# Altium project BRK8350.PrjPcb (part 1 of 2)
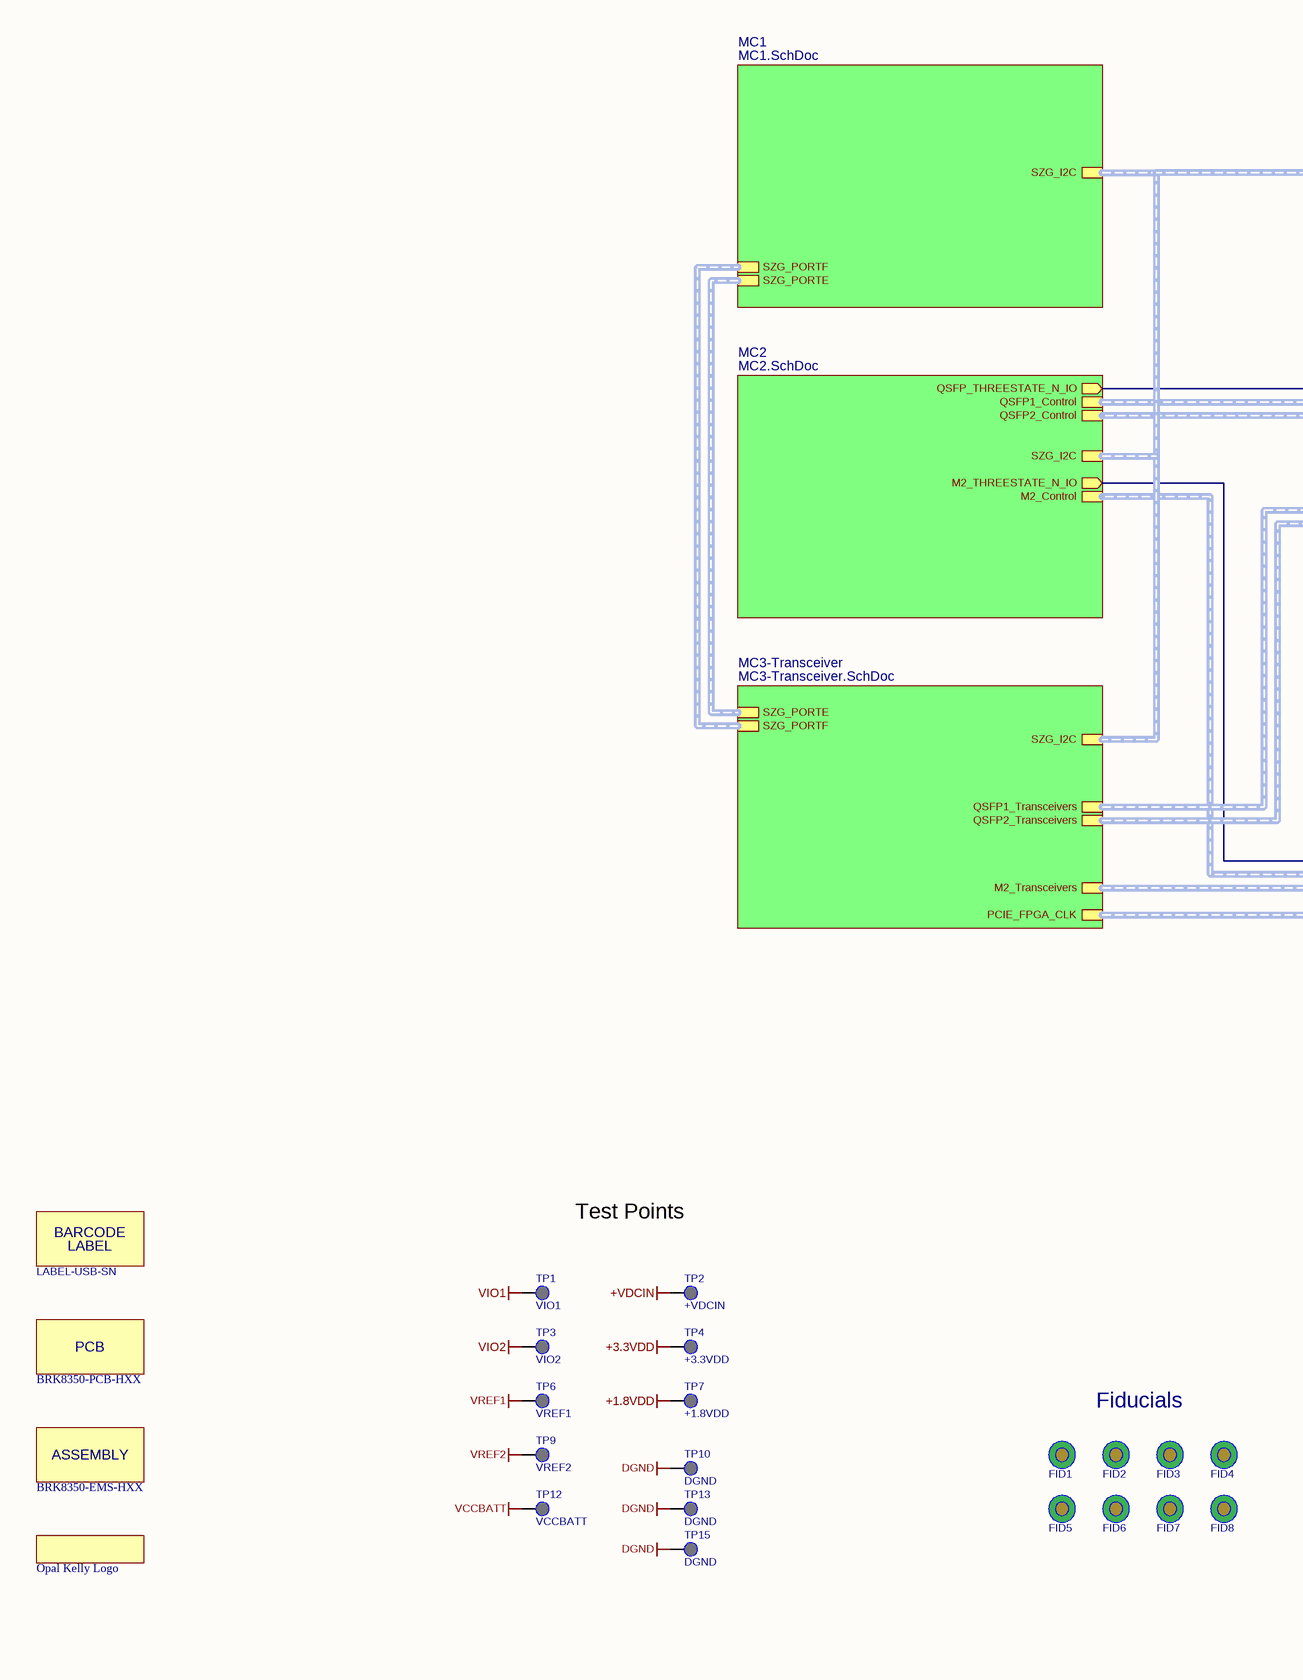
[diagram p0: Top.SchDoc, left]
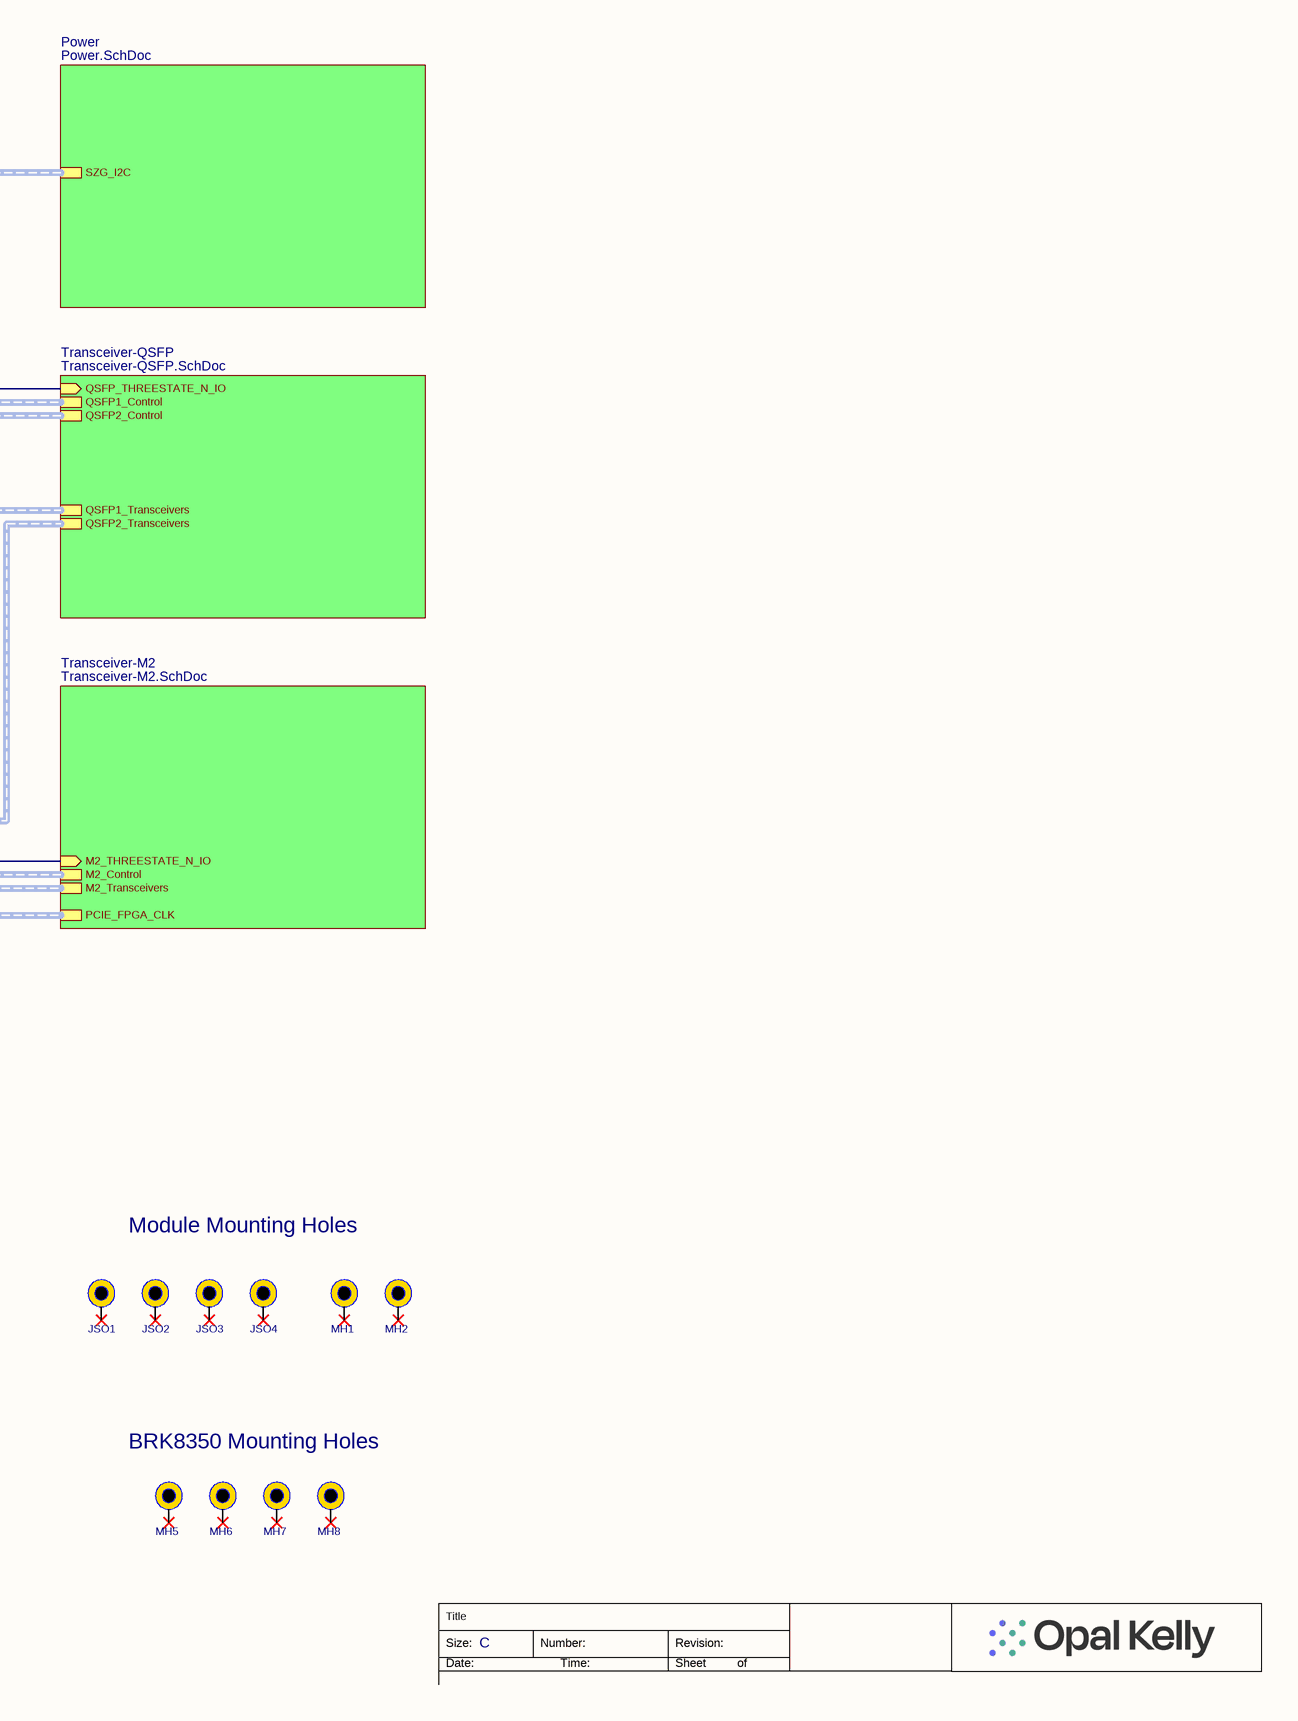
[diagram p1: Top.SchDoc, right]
VariantBoms: Default=001770; PCB_Revision: H; Part_Number: BRK8350; BOM_Revision: 02
7 sheets, 293 parts. Net scope: hierarchical (ports join the sheet entries above them; power ports are global).
Board file: BRK8350.PcbDoc
Sheets:
  Top.SchDoc
    Transceiver-QSFP = Transceiver-QSFP.SchDoc
    MC2 = MC2.SchDoc
    MC1 = MC1.SchDoc
    Power = Power.SchDoc
    Transceiver-M2 = Transceiver-M2.SchDoc
    MC3-Transceiver = MC3-Transceiver.SchDoc

## Sheet Top.SchDoc: BRK8350 - Top Level
size C; Organization: Opal Kelly; Address1: 13500 SW 72nd Ave STE 100; Address3: Portland, OR  97223; Address4: http://www.opalkelly.com; DocumentNumber: 1; Revision: 1; SheetNumber: 1; SheetTotal: 7; PageSetup: Record=PageOptions¦CenterHorizontal=True¦CenterVertical=True¦PrintScale=0.52¦XCorrection=1.00¦YCorrection=1.00¦PrintKind=0¦BorderSize=5000000¦LeftOffset=0¦BottomOffset=0¦Orientation=2¦PaperLength=1000¦PaperWidth=1000¦Scale=100¦PaperSource=15¦PrintQuality=600¦MediaType=1¦DitherType=10¦PaperKind=Letter¦PrintScaleMode=1

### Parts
*1  Opal Kelly Logo  [okLogo-23x5-2021]
ASSY1  BRK8350-EMS-HXX  (mechanical)
FID1  FIDUCIAL  [FID1MM/2MM-SS]  (value not drawn)
FID2  FIDUCIAL  [FID1MM/2MM-SS]  (value not drawn)
FID3  FIDUCIAL  [FID1MM/2MM-SS]  (value not drawn)
FID4  FIDUCIAL  [FID1MM/2MM-SS]  (value not drawn)
FID5  FIDUCIAL  [FID1MM/2MM-SS]  (value not drawn)
FID6  FIDUCIAL  [FID1MM/2MM-SS]  (value not drawn)
FID7  FIDUCIAL  [FID1MM/2MM-SS]  (value not drawn)
FID8  FIDUCIAL  [FID1MM/2MM-SS]  (value not drawn)
JSO1  Jack Screw Standoff  [JSO-0515-01]  (value not drawn)
JSO2  Jack Screw Standoff  [JSO-0515-01]  (value not drawn)
JSO3  Jack Screw Standoff  [JSO-0515-01]  (value not drawn)
JSO4  Jack Screw Standoff  [JSO-0515-01]  (value not drawn)
LABEL1  LABEL-USB-SN  (mechanical)
MH1  MTG  [MTG-3.2/6.5-PTH]  (value not drawn)
MH2  MTG  [MTG-3.2/6.5-PTH]  (value not drawn)
MH5  MTG  [MTG-3.2/6.5-PTH]  (value not drawn)
MH6  MTG  [MTG-3.2/6.5-PTH]  (value not drawn)
MH7  MTG  [MTG-3.2/6.5-PTH]  (value not drawn)
MH8  MTG  [MTG-3.2/6.5-PTH]  (value not drawn)
PCB1  BRK8350-PCB-HXX  (mechanical)
TP1  VIO1  [TP-PTH-65/100]
TP2  +VDCIN  [TP-PTH-65/100]
TP3  VIO2  [TP-PTH-65/100]
TP4  +3.3VDD  [TP-PTH-65/100]
TP6  VREF1  [TP-PTH-65/100]
TP7  +1.8VDD  [TP-PTH-65/100]
TP9  VREF2  [TP-PTH-65/100]
TP10  DGND  [TP-PTH-65/100]
TP12  VCCBATT  [TP-PTH-65/100]
TP13  DGND  [TP-PTH-65/100]
TP15  DGND  [TP-PTH-65/100]

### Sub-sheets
MC1 = MC1.SchDoc: SZG_I2C (harness I2C), SZG_PORTF (harness SYZYGY_TXR4), SZG_PORTE (harness SYZYGY_TXR4)
MC2 = MC2.SchDoc: QSFP1_Control (harness QSFP_Control), M2_Control (harness M2_Control), QSFP2_Control (harness QSFP_Control), SZG_I2C (harness I2C), QSFP_THREESTATE_N_IO (out), M2_THREESTATE_N_IO (out)
MC3-Transceiver = MC3-Transceiver.SchDoc: SZG_PORTF (harness SYZYGY_TXR4), SZG_PORTE (harness SYZYGY_TXR4), SZG_I2C (harness I2C), M2_Transceivers (harness M2_Transceivers), QSFP1_Transceivers (harness QSFP_Transceivers), QSFP2_Transceivers (harness QSFP_Transceivers), PCIE_FPGA_CLK (harness CLK)
Power = Power.SchDoc: SZG_I2C (harness I2C)
Transceiver-M2 = Transceiver-M2.SchDoc: M2_Transceivers (harness M2_Transceivers), M2_Control (harness M2_Control), PCIE_FPGA_CLK (harness CLK), M2_THREESTATE_N_IO (in)
Transceiver-QSFP = Transceiver-QSFP.SchDoc: QSFP1_Control (harness QSFP_Control), QSFP2_Control (harness QSFP_Control), QSFP1_Transceivers (harness QSFP_Transceivers), QSFP2_Transceivers (harness QSFP_Transceivers), QSFP_THREESTATE_N_IO (in)

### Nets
+1.8VDD: TP7.1(PIN)
+3.3VDD: TP4.1(PIN)
+VDCIN: TP2.1(PIN)
DGND: TP10.1(PIN) TP13.1(PIN) TP15.1(PIN)
VCCBATT: TP12.1(PIN)
VIO1: TP1.1(PIN)
VIO2: TP3.1(PIN)
VREF1: TP6.1(PIN)
VREF2: TP9.1(PIN)
M2_THREESTATE_N_IO: sheet MC2/M2_THREESTATE_N_IO, sheet Transceiver-M2/M2_THREESTATE_N_IO
QSFP_THREESTATE_N_IO: sheet Transceiver-QSFP/QSFP_THREESTATE_N_IO, sheet MC2/QSFP_THREESTATE_N_IO

Not connected (* = marked no-connect by the designer): JSO1 1*; JSO2 1*; JSO3 1*; JSO4 1*; MH1 1*; MH2 1*; MH5 1*; MH6 1*; MH7 1*; MH8 1*

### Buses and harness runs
harness sheet MC1/SZG_I2C = sheet MC2/SZG_I2C = sheet MC3-Transceiver/SZG_I2C = sheet Power/SZG_I2C
harness sheet MC1/SZG_PORTE = sheet MC3-Transceiver/SZG_PORTE
harness sheet MC1/SZG_PORTF = sheet MC3-Transceiver/SZG_PORTF
harness sheet MC2/M2_Control = sheet Transceiver-M2/M2_Control
harness sheet MC2/QSFP1_Control = sheet Transceiver-QSFP/QSFP1_Control
harness sheet MC2/QSFP2_Control = sheet Transceiver-QSFP/QSFP2_Control
harness sheet MC3-Transceiver/M2_Transceivers = sheet Transceiver-M2/M2_Transceivers
harness sheet MC3-Transceiver/PCIE_FPGA_CLK = sheet Transceiver-M2/PCIE_FPGA_CLK
harness sheet MC3-Transceiver/QSFP1_Transceivers = sheet Transceiver-QSFP/QSFP1_Transceivers
harness sheet MC3-Transceiver/QSFP2_Transceivers = sheet Transceiver-QSFP/QSFP2_Transceivers

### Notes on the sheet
- Test Points
- Module Mounting Holes
- Fiducials
- BRK8350 Mounting Holes
- Title
- Size:
- Date:
- C
- Number:
- Time:
- Revision:
- Sheet
- of

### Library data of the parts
*1 = OKLOGO: partnumber: ALIGNI_IGNORE
ASSY1 = 002490: BRK8350 PCB assembly; Partnumber: 002490; Manufacturer: PCB Assembly Cost
FID1-FID8 = FIDUCIAL: PCB fiducial; partnumber: ALIGNI_IGNORE
JSO1-JSO4 = 001879: Mounting hole; Partnumber: 001879; manufacturer: Samtec
LABEL1 = 000605: Barcode label; Partnumber: 000605; manufacturer: Generic Printer
MH1 MH2 MH5-MH8 = MTG: Mounting hole; partnumber: ALIGNI_IGNORE
PCB1 = 002491: PCB for BRK8350; Partnumber: 002491; Manufacturer: Generic PCB Manufacturer
TP1-TP4 TP6 TP7 TP9 TP10 TP12 TP13 TP15 = TP-PTH-65/100: Test point, plated through-hole, 65/100mil; partnumber: ALIGNI_IGNORE

## Sheet Transceiver-QSFP.SchDoc: BRK8350 - QSFP
size C; Author: Casey Smith; Organization: Opal Kelly; Address1: 13500 SW 72nd Ave STE 100; Address2: Portland, OR 97223; Address3: 217.391.3724; Address4: http://www.opalkelly.com; DocumentNumber: 5; Revision: 1; SheetNumber: 5; SheetTotal: 7
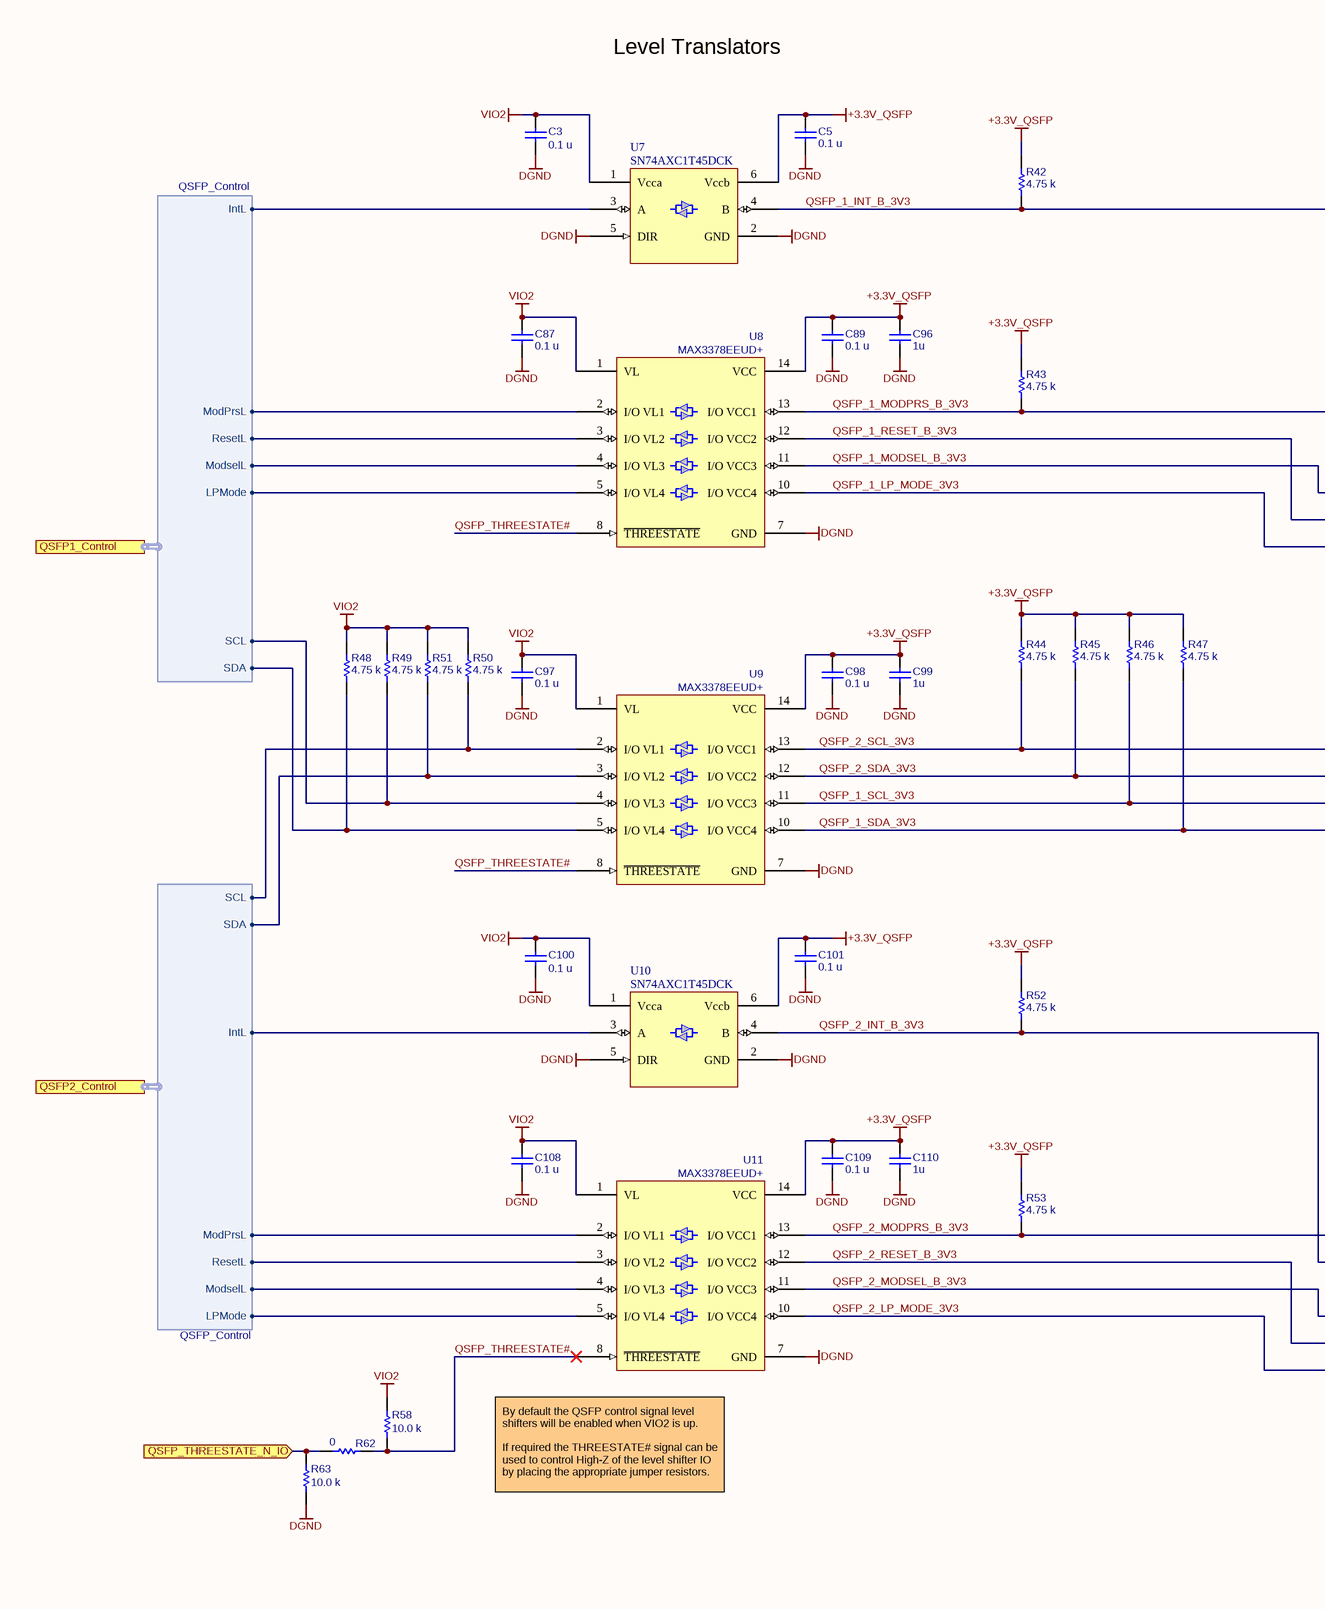
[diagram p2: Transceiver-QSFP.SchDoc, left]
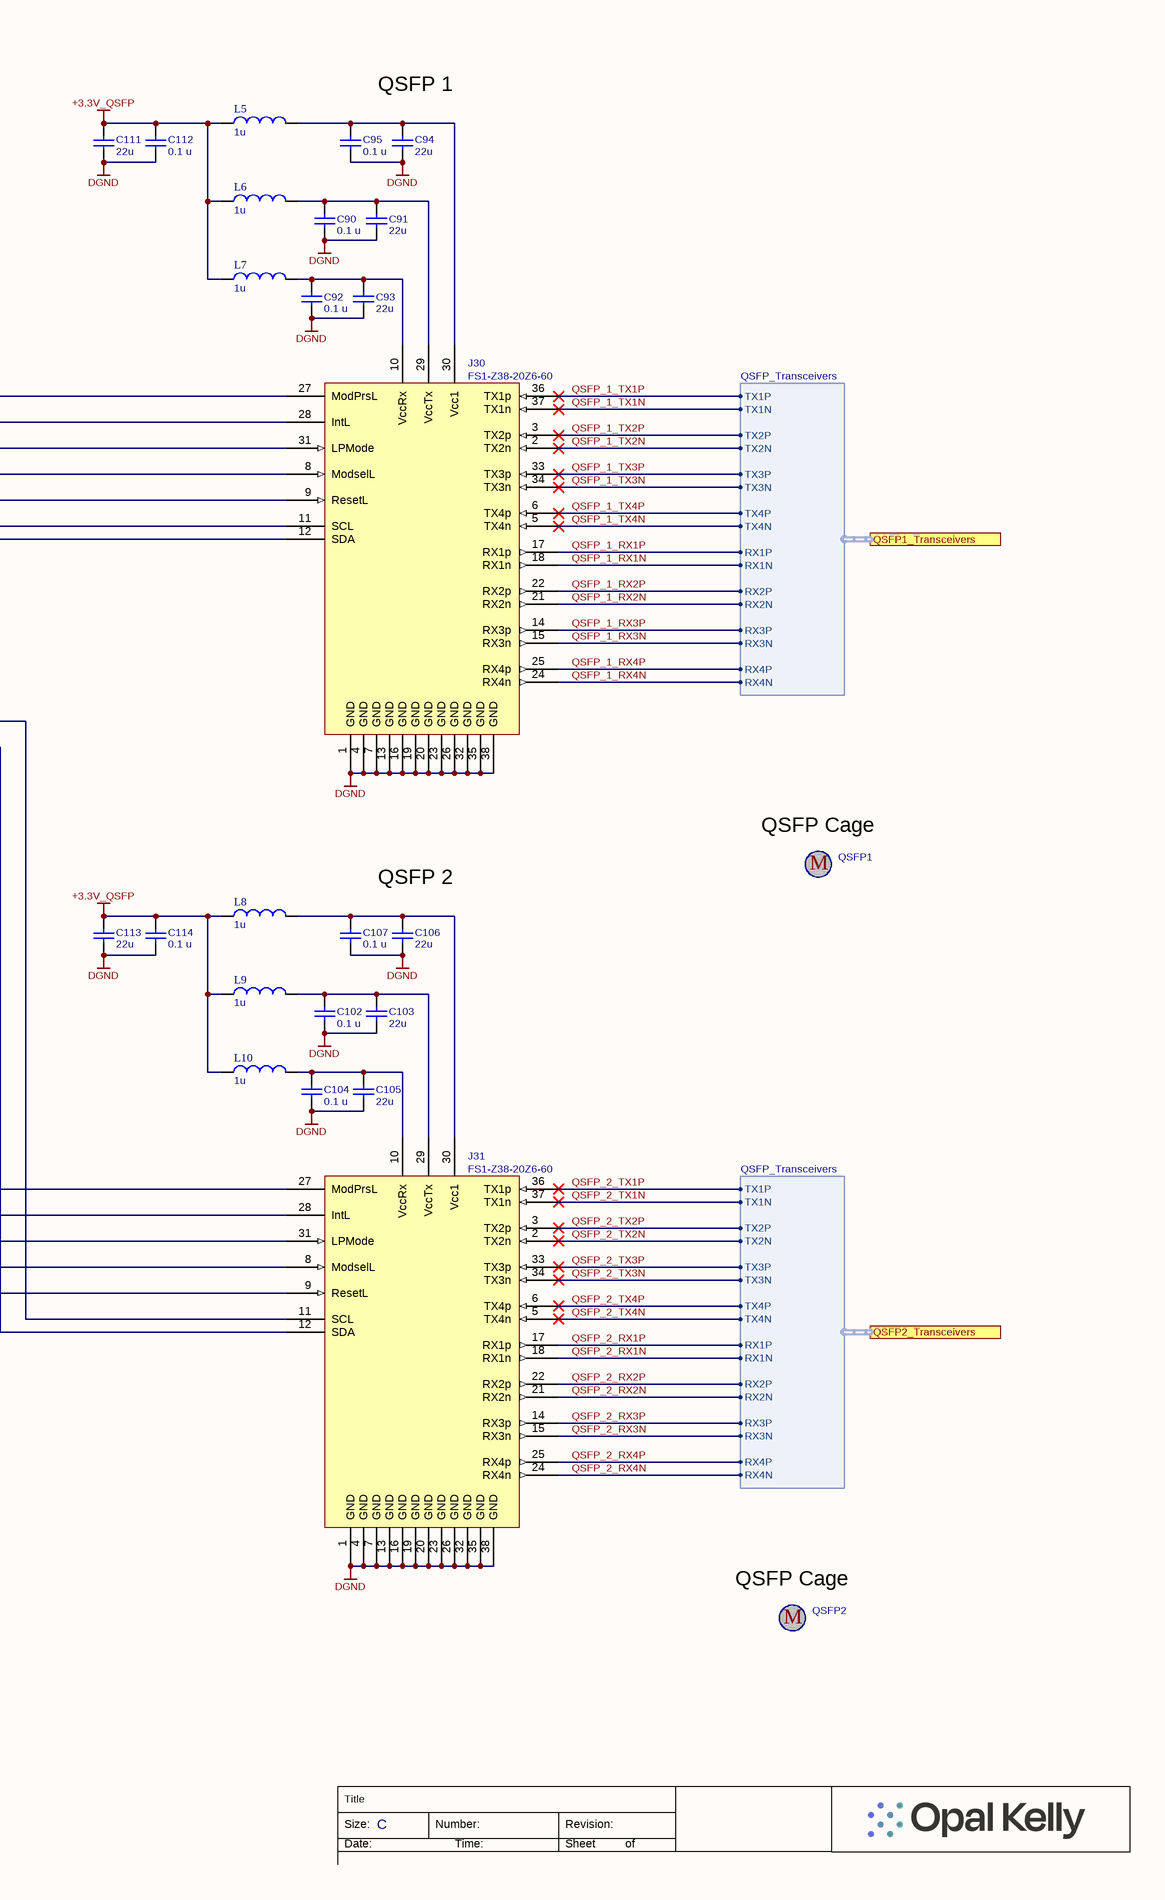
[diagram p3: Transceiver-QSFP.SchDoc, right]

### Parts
C3  value 0.1 u  [CAPC1005X06A]  (hidden comment: C0402C104K8PACTU)
C5  value 0.1 u  [CAPC1005X06A]  (hidden comment: C0402C104K8PACTU)
C87  value 0.1 u  [CAPC1005X06A]  (hidden comment: C0402C104K8PACTU)
C89  value 0.1 u  [CAPC1005X06A]  (hidden comment: C0402C104K8PACTU)
C90  value 0.1 u  [CAPC1005X06A]  (hidden comment: SM-0402, 10%, 10v)
C91  value 22u  [CAPC3216N]  (hidden comment: SM-1206, 10%, 10v, X7R)
C92  value 0.1 u  [CAPC1005X06A]  (hidden comment: SM-0402, 10%, 10v)
C93  value 22u  [CAPC3216N]  (hidden comment: SM-1206, 10%, 10v, X7R)
C94  value 22u  [CAPC3216N]  (hidden comment: SM-1206, 10%, 10v, X7R)
C95  value 0.1 u  [CAPC1005X06A]  (hidden comment: SM-0402, 10%, 10v)
C96  value 1u  [CAPC1005X06A]  (hidden comment: LMK105BJ105KV-F)
C97  value 0.1 u  [CAPC1005X06A]  (hidden comment: C0402C104K8PACTU)
C98  value 0.1 u  [CAPC1005X06A]  (hidden comment: C0402C104K8PACTU)
C99  value 1u  [CAPC1005X06A]  (hidden comment: LMK105BJ105KV-F)
C100  value 0.1 u  [CAPC1005X06A]  (hidden comment: C0402C104K8PACTU)
C101  value 0.1 u  [CAPC1005X06A]  (hidden comment: C0402C104K8PACTU)
C102  value 0.1 u  [CAPC1005X06A]  (hidden comment: SM-0402, 10%, 10v)
C103  value 22u  [CAPC3216N]  (hidden comment: SM-1206, 10%, 10v, X7R)
C104  value 0.1 u  [CAPC1005X06A]  (hidden comment: SM-0402, 10%, 10v)
C105  value 22u  [CAPC3216N]  (hidden comment: SM-1206, 10%, 10v, X7R)
C106  value 22u  [CAPC3216N]  (hidden comment: SM-1206, 10%, 10v, X7R)
C107  value 0.1 u  [CAPC1005X06A]  (hidden comment: SM-0402, 10%, 10v)
C108  value 0.1 u  [CAPC1005X06A]  (hidden comment: C0402C104K8PACTU)
C109  value 0.1 u  [CAPC1005X06A]  (hidden comment: C0402C104K8PACTU)
C110  value 1u  [CAPC1005X06A]  (hidden comment: LMK105BJ105KV-F)
C111  value 22u  [CAPC3216N]  (hidden comment: SM-1206, 10%, 10v, X7R)
C112  value 0.1 u  [CAPC1005X06A]  (hidden comment: SM-0402, 10%, 10v)
C113  value 22u  [CAPC3216N]  (hidden comment: SM-1206, 10%, 10v, X7R)
C114  value 0.1 u  [CAPC1005X06A]  (hidden comment: SM-0402, 10%, 10v)
J30  FS1-Z38-20Z6-60  [QSFP28_RECEPTACLE_SFF-8679]
J31  FS1-Z38-20Z6-60  [QSFP28_RECEPTACLE_SFF-8679]
L5  value 1u  [CIGT252010]  (hidden comment: CIGT252010LM1R0MNE)
L6  value 1u  [CIGT252010]  (hidden comment: CIGT252010LM1R0MNE)
L7  value 1u  [CIGT252010]  (hidden comment: CIGT252010LM1R0MNE)
L8  value 1u  [CIGT252010]  (hidden comment: CIGT252010LM1R0MNE)
L9  value 1u  [CIGT252010]  (hidden comment: CIGT252010LM1R0MNE)
L10  value 1u  [CIGT252010]  (hidden comment: CIGT252010LM1R0MNE)
QSFP1  Pressfit  [QSFP28_SINGLE_CAGE]  (value not drawn)
QSFP2  Pressfit  [QSFP28_SINGLE_CAGE]  (value not drawn)
R42  value 4.75 k  [RESC1005X06A]  (hidden comment: CRCW04024K75FKED)
R43  value 4.75 k  [RESC1005X06A]  (hidden comment: CRCW04024K75FKED)
R44  value 4.75 k  [RESC1005X06A]  (hidden comment: CRCW04024K75FKED)
R45  value 4.75 k  [RESC1005X06A]  (hidden comment: CRCW04024K75FKED)
R46  value 4.75 k  [RESC1005X06A]  (hidden comment: CRCW04024K75FKED)
R47  value 4.75 k  [RESC1005X06A]  (hidden comment: CRCW04024K75FKED)
R48  value 4.75 k  [RESC1005X06A]  (hidden comment: CRCW04024K75FKED)
R49  value 4.75 k  [RESC1005X06A]  (hidden comment: CRCW04024K75FKED)
R50  value 4.75 k  [RESC1005X06A]  (hidden comment: CRCW04024K75FKED)
R51  value 4.75 k  [RESC1005X06A]  (hidden comment: CRCW04024K75FKED)
R52  value 4.75 k  [RESC1005X06A]  (hidden comment: CRCW04024K75FKED)
R53  value 4.75 k  [RESC1005X06A]  (hidden comment: CRCW04024K75FKED)
R58  value 10.0 k  [RESC1005X06A]  (hidden comment: CRCW040210K0FKED)
R62  value 0  [RESC1005X06A]  (hidden comment: SM-0402, 1%, 1/16W)
R63  value 10.0 k  [RESC1005X06A]  (hidden comment: CRCW040210K0FKED)
U7  SN74AXC1T45DCK  [DCK-R-PDSO-G6]
U8  MAX3378EEUD+  [MAX3378EEUD+]
U9  MAX3378EEUD+  [MAX3378EEUD+]
U10  SN74AXC1T45DCK  [DCK-R-PDSO-G6]
U11  MAX3378EEUD+  [MAX3378EEUD+]

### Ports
QSFP1_Control (harness QSFP_Control), QSFP1_Transceivers (harness QSFP_Transceivers), QSFP2_Control (harness QSFP_Control), QSFP2_Transceivers (harness QSFP_Transceivers), QSFP_THREESTATE_N_IO (in)

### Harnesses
QSFP_Transceivers: TX1P, TX1N, TX2P, TX2N, TX3P, TX3N, TX4P, TX4N, RX1P, RX1N, RX2P, RX2N, RX3P, RX3N, RX4P, RX4N
QSFP_Control: ModPrsL, IntL, LPMode, ModselL, ResetL, SCL, SDA

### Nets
+3.3V_QSFP: C5.2 C89.2 C96.2 C98.2 C99.2 C101.2 C109.2 C110.2 C111.2 C112.2 C113.2 C114.2 L5.1 L6.1 L7.1 L8.1 L9.1 L10.1 R42.2 R43.2 R44.2 R45.2 R46.2 R47.2 R52.2 R53.2 U7.6(Vccb) U8.14(VCC) U9.14(VCC) U10.6(Vccb) U11.14(VCC)
DGND: C3.1 C5.1 C87.1 C89.1 C90.1 C91.1 C92.1 C93.1 C94.1 C95.1 C96.1 C97.1 C98.1 C99.1 C100.1 C101.1 C102.1 C103.1 C104.1 C105.1 C106.1 C107.1 C108.1 C109.1 C110.1 C111.1 C112.1 C113.1 C114.1 J30.1(GND) J30.4(GND) J30.7(GND) J30.13(GND) J30.16(GND) J30.19(GND) J30.20(GND) J30.23(GND) J30.26(GND) J30.32(GND) J30.35(GND) J30.38(GND) J31.1(GND) J31.4(GND) J31.7(GND) J31.13(GND) J31.16(GND) J31.19(GND) J31.20(GND) J31.23(GND) J31.26(GND) J31.32(GND) J31.35(GND) J31.38(GND) R63.1 U7.2(GND) U7.5(DIR) U8.7(GND) U9.7(GND) U10.2(GND) U10.5(DIR) U11.7(GND)
VIO2: C3.2 C87.2 C97.2 C100.2 C108.2 R48.2 R49.2 R50.2 R51.2 R58.2 U7.1(Vcca) U8.1(VL) U9.1(VL) U10.1(Vcca) U11.1(VL)
QSFP_1_INT_B: U7.3(A) ; port QSFP1_Control.IntL
QSFP_1_INT_B_3V3: J30.28(IntL) R42.1 U7.4(B)
QSFP_1_LP_MODE: U8.5(I/O_VL4) ; port QSFP1_Control.LPMode
QSFP_1_LP_MODE_3V3: J30.31(LPMode) U8.10(I/O_VCC4)
QSFP_1_MODPRS_B: U8.2(I/O_VL1) ; port QSFP1_Control.ModPrsL
QSFP_1_MODPRS_B_3V3: J30.27(ModPrsL) R43.1 U8.13(I/O_VCC1)
QSFP_1_MODSEL_B: U8.4(I/O_VL3) ; port QSFP1_Control.ModselL
QSFP_1_MODSEL_B_3V3: J30.8(ModselL) U8.11(I/O_VCC3)
QSFP_1_RESET_B: U8.3(I/O_VL2) ; port QSFP1_Control.ResetL
QSFP_1_RESET_B_3V3: J30.9(ResetL) U8.12(I/O_VCC2)
QSFP_1_RX1N: J30.18(RX1n) ; port QSFP1_Transceivers.RX1N
QSFP_1_RX1P: J30.17(RX1p) ; port QSFP1_Transceivers.RX1P
QSFP_1_RX2N: J30.21(RX2n) ; port QSFP1_Transceivers.RX2N
QSFP_1_RX2P: J30.22(RX2p) ; port QSFP1_Transceivers.RX2P
QSFP_1_RX3N: J30.15(RX3n) ; port QSFP1_Transceivers.RX3N
QSFP_1_RX3P: J30.14(RX3p) ; port QSFP1_Transceivers.RX3P
QSFP_1_RX4N: J30.24(RX4n) ; port QSFP1_Transceivers.RX4N
QSFP_1_RX4P: J30.25(RX4p) ; port QSFP1_Transceivers.RX4P
QSFP_1_SCL: R49.1 U9.4(I/O_VL3) ; port QSFP1_Control.SCL
QSFP_1_SCL_3V3: J30.11(SCL) R46.1 U9.11(I/O_VCC3)
QSFP_1_SDA: R48.1 U9.5(I/O_VL4) ; port QSFP1_Control.SDA
QSFP_1_SDA_3V3: J30.12(SDA) R47.1 U9.10(I/O_VCC4)
QSFP_1_TX1N: J30.37(TX1n) ; port QSFP1_Transceivers.TX1N
QSFP_1_TX1P: J30.36(TX1p) ; port QSFP1_Transceivers.TX1P
QSFP_1_TX2N: J30.2(TX2n) ; port QSFP1_Transceivers.TX2N
QSFP_1_TX2P: J30.3(TX2p) ; port QSFP1_Transceivers.TX2P
QSFP_1_TX3N: J30.34(TX3n) ; port QSFP1_Transceivers.TX3N
QSFP_1_TX3P: J30.33(TX3p) ; port QSFP1_Transceivers.TX3P
QSFP_1_TX4N: J30.5(TX4n) ; port QSFP1_Transceivers.TX4N
QSFP_1_TX4P: J30.6(TX4p) ; port QSFP1_Transceivers.TX4P
QSFP_2_INT_B: U10.3(A) ; port QSFP2_Control.IntL
QSFP_2_INT_B_3V3: J31.28(IntL) R52.1 U10.4(B)
QSFP_2_LP_MODE: U11.5(I/O_VL4) ; port QSFP2_Control.LPMode
QSFP_2_LP_MODE_3V3: J31.31(LPMode) U11.10(I/O_VCC4)
QSFP_2_MODPRS_B: U11.2(I/O_VL1) ; port QSFP2_Control.ModPrsL
QSFP_2_MODPRS_B_3V3: J31.27(ModPrsL) R53.1 U11.13(I/O_VCC1)
QSFP_2_MODSEL_B: U11.4(I/O_VL3) ; port QSFP2_Control.ModselL
QSFP_2_MODSEL_B_3V3: J31.8(ModselL) U11.11(I/O_VCC3)
QSFP_2_RESET_B: U11.3(I/O_VL2) ; port QSFP2_Control.ResetL
QSFP_2_RESET_B_3V3: J31.9(ResetL) U11.12(I/O_VCC2)
QSFP_2_RX1N: J31.18(RX1n) ; port QSFP2_Transceivers.RX1N
QSFP_2_RX1P: J31.17(RX1p) ; port QSFP2_Transceivers.RX1P
QSFP_2_RX2N: J31.21(RX2n) ; port QSFP2_Transceivers.RX2N
QSFP_2_RX2P: J31.22(RX2p) ; port QSFP2_Transceivers.RX2P
QSFP_2_RX3N: J31.15(RX3n) ; port QSFP2_Transceivers.RX3N
QSFP_2_RX3P: J31.14(RX3p) ; port QSFP2_Transceivers.RX3P
QSFP_2_RX4N: J31.24(RX4n) ; port QSFP2_Transceivers.RX4N
QSFP_2_RX4P: J31.25(RX4p) ; port QSFP2_Transceivers.RX4P
QSFP_2_SCL: R50.1 U9.2(I/O_VL1) ; port QSFP2_Control.SCL
QSFP_2_SCL_3V3: J31.11(SCL) R44.1 U9.13(I/O_VCC1)
QSFP_2_SDA: R51.1 U9.3(I/O_VL2) ; port QSFP2_Control.SDA
QSFP_2_SDA_3V3: J31.12(SDA) R45.1 U9.12(I/O_VCC2)
QSFP_2_TX1N: J31.37(TX1n) ; port QSFP2_Transceivers.TX1N
QSFP_2_TX1P: J31.36(TX1p) ; port QSFP2_Transceivers.TX1P
QSFP_2_TX2N: J31.2(TX2n) ; port QSFP2_Transceivers.TX2N
QSFP_2_TX2P: J31.3(TX2p) ; port QSFP2_Transceivers.TX2P
QSFP_2_TX3N: J31.34(TX3n) ; port QSFP2_Transceivers.TX3N
QSFP_2_TX3P: J31.33(TX3p) ; port QSFP2_Transceivers.TX3P
QSFP_2_TX4N: J31.5(TX4n) ; port QSFP2_Transceivers.TX4N
QSFP_2_TX4P: J31.6(TX4p) ; port QSFP2_Transceivers.TX4P
QSFP_THREESTATE#: R58.1 R62.2 U8.8(~{THREESTATE}) U9.8(~{THREESTATE}) U11.8(~{THREESTATE})
QSFP_THREESTATE_N_IO: R62.1 R63.2 ; port QSFP_THREESTATE_N_IO
NetC90_2: C90.2 C91.2 J30.29(VccTx) L6.2
NetC92_2: C92.2 C93.2 J30.10(VccRx) L7.2
NetC94_2: C94.2 C95.2 J30.30(Vcc1) L5.2
NetC102_2: C102.2 C103.2 J31.29(VccTx) L9.2
NetC104_2: C104.2 C105.2 J31.10(VccRx) L10.2
NetC106_2: C106.2 C107.2 J31.30(Vcc1) L8.2

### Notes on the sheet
- Level Translators
- QSFP 1
- QSFP 2
- (near QSFP1) QSFP Cage
- (near U11) By default the QSFP control signal level shifters will be enabled when VIO2 is up.
  If required the THREESTATE# signal can be used to control High-Z of the level shifter IO by placing the appropriate jumper resistors.
- (near QSFP2) QSFP Cage
- Title
- Size:
- Date:
- C
- Number:
- Time:
- Revision:
- Sheet
- of

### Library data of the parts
C3 C5 C100 C101 = 001073: Partnumber: 000070; manufacturer: Kemet; ValueFloat: 1E-7; x_tolerance: 10
C87 C89 C97 C98 C108 C109 = 000070: Partnumber: 000070; manufacturer: Kemet; ValueFloat: 1E-7; x_tolerance: 10
C90 C92 C95 C102 C104 C107 C112 C114 = 000070: Partnumber: 000070; manufacturer: Kemet; manufacturer_pn: C0402C104K8PACTU; ValueFloat: 1E-7; id: 750; inventory_price: 0.0023; reorder_quantity: 70000; x_tolerance: 10
C91 C93 C94 C103 C105 C106 C111 C113 = 001284: Partnumber: 001284; manufacturer: Taiyo Yuden; manufacturer_pn: LMK316AB7226KL-TR; ValueFloat: 2.2E-5; id: 60625; inventory_price: 0.14; reorder_quantity: 4000; x_tolerance: 10
C96 C99 C110 = 000480: Partnumber: 000480; manufacturer: Taiyo Yuden; ValueFloat: 1E-6; x_tolerance: 10
J30 J31 = 001782: Partnumber: 001782; manufacturer: Amphenol; id: 254667; inventory_price: 4
L5-L10 = 002331: Thin Film, 1uH, 3.1A, 50mOhm, Unshielded; Partnumber: 002331; Manufacturer: Samsung Electro-Mechanics; ValueFloat: 1E-6; Tolerance (%): 20; Description 2: 1008 (2520 Metric)
QSFP1 QSFP2 = 001781: Partnumber: 001781; manufacturer: Amphenol; manufacturer_pn: U95-T111-1001; id: 254666; inventory_price: 3.5
R42-R53 = 001008: Partnumber: 001008; manufacturer: Vishay; ValueFloat: 4750; x_tolerance: 1
R58 R63 = 001521: Thick-film resistor; Manufacturer: Vishay; partnumber: 001521; Description 2: SM-0402, 1%, 1/16W; ValueFloat: 10000; Tolerance (%): 1; x_lifecycle_status: Production
R62 = 001713: Partnumber: 001713; manufacturer: Vishay; manufacturer_pn: CRCW04020000Z0EDC; id: 219362; inventory_price: 0.004; reorder_quantity: 20000; x_tolerance: 1
U7 U10 = 002140: Level Translator, 0.65V - 3.6V, Direction Control; Partnumber: 002140; Manufacturer: Texas Instruments; Description 2: Single Bit, Dual Supplies
U8 U9 U11 = 000178: Partnumber: 000178; manufacturer: Maxim

## Sheet MC2.SchDoc: BRK8350 - Mezzanine Connector MC2
size C; Author: Casey Smith; Organization: Opal Kelly; Address1: 13500 SW 72nd Ave STE 100; Address2: Portland, OR 97223; Address3: 217.391.3724; Address4: http://www.opalkelly.com; DocumentNumber: 3; Revision: 1; SheetNumber: 3; SheetTotal: 7
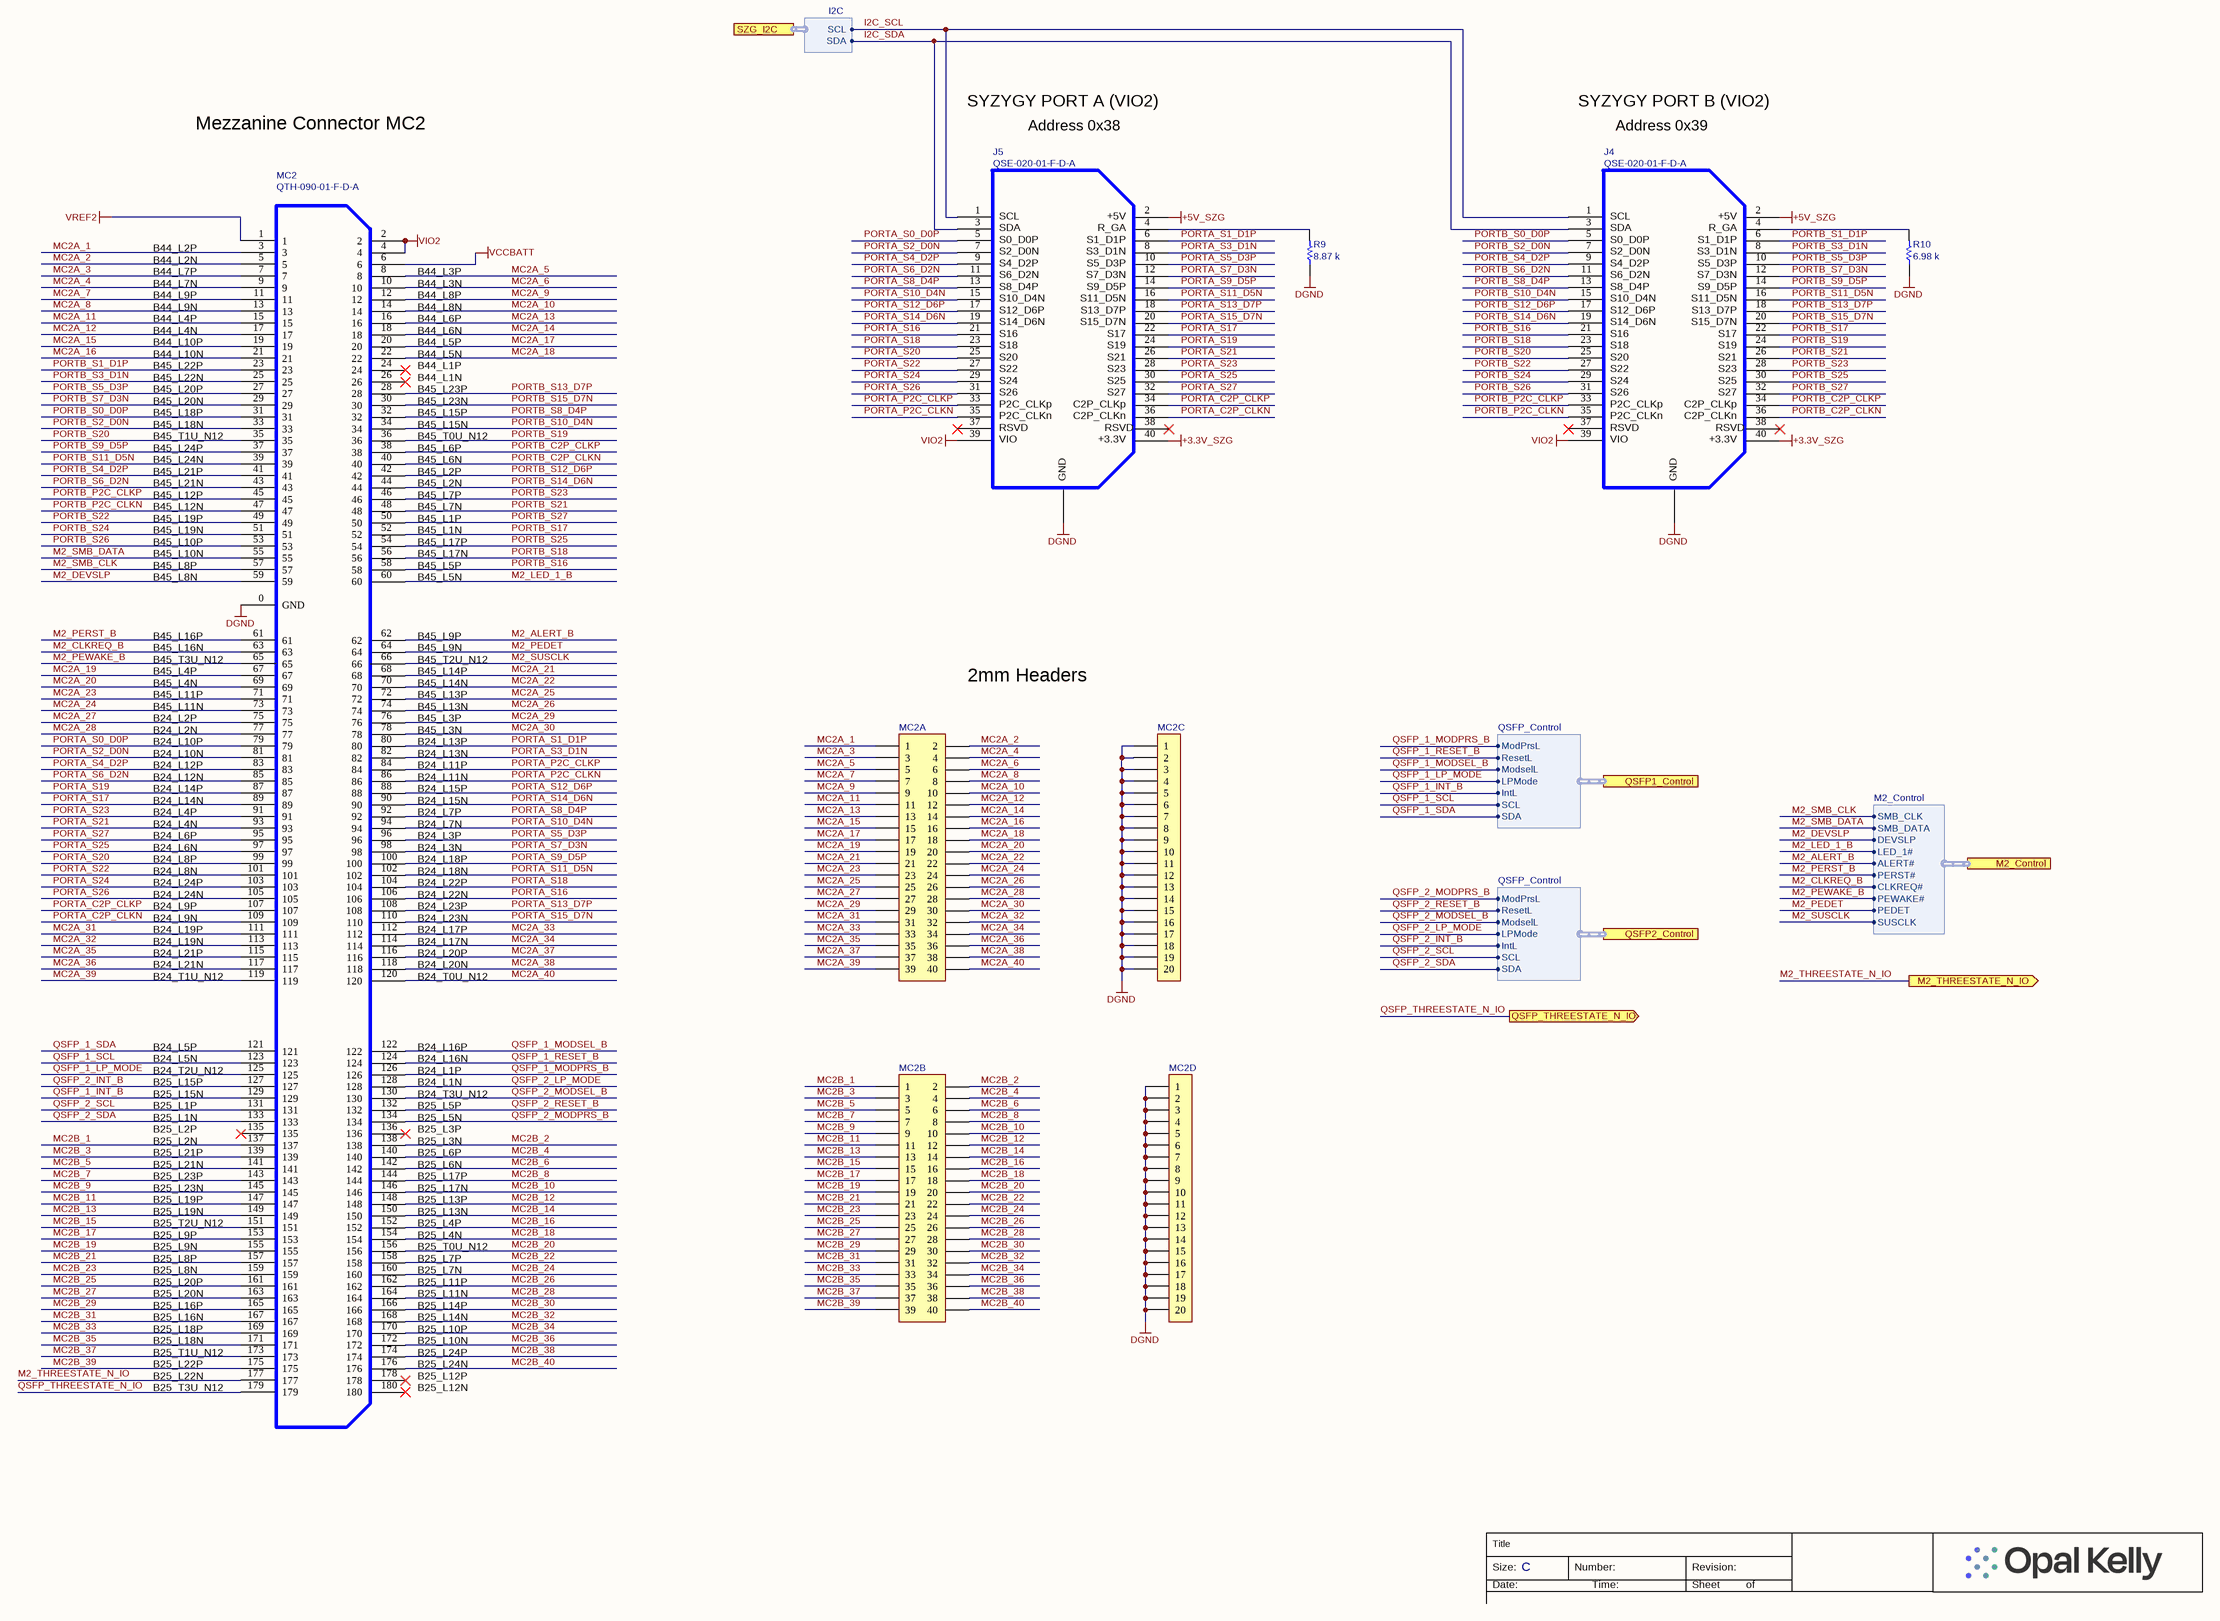
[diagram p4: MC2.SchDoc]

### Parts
J4  QSE-020-01-F-D-A  [QSE-020-01-X-D-A-L-SYZYGY]
J5  QSE-020-01-F-D-A  [QSE-020-01-X-D-A-L-SYZYGY]
MC2  QTH-090-01-F-D-A  [QTH-090-01-X-D]
MC2A  0877584016  [HDR2X20-2MM]  (value not drawn)
MC2B  0877584016  [HDR2X20-2MM]  (value not drawn)
MC2C  Header, 20-Pin, Single Row  [HDR1X20-2MM]  (value not drawn)
MC2D  Header, 20-Pin, Single Row  [HDR1X20-2MM]  (value not drawn)
R9  value 8.87 k  [RESC1005X06A]  (hidden comment: RC0402FR-078K87L)
R10  value 6.98 k  [RESC1005X06A]  (hidden comment: RC0402FR-076K98L)

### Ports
M2_Control (harness M2_Control), M2_THREESTATE_N_IO (out), QSFP1_Control (harness QSFP_Control), QSFP2_Control (harness QSFP_Control), QSFP_THREESTATE_N_IO (out), SZG_I2C (harness I2C)

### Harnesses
I2C: SCL, SDA
M2_Control: DEVSLP, SMB_CLK, SMB_DATA, ALERT#, PERST#, CLKREQ#, PEWAKE#, LED_1#, SUSCLK, PEDET
QSFP_Control: ModPrsL, IntL, LPMode, ModselL, ResetL, SCL, SDA

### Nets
+3.3V_SZG: J4.40 J5.40
+5V_SZG: J4.2 J5.2
DGND: J4.0 J5.0 MC2.0(GND) MC2C.1 MC2C.2 MC2C.3 MC2C.4 MC2C.5 MC2C.6 MC2C.7 MC2C.8 MC2C.9 MC2C.10 MC2C.11 MC2C.12 MC2C.13 MC2C.14 MC2C.15 MC2C.16 MC2C.17 MC2C.18 MC2C.19 MC2C.20 MC2D.1 MC2D.2 MC2D.3 MC2D.4 MC2D.5 MC2D.6 MC2D.7 MC2D.8 MC2D.9 MC2D.10 MC2D.11 MC2D.12 MC2D.13 MC2D.14 MC2D.15 MC2D.16 MC2D.17 MC2D.18 MC2D.19 MC2D.20 R9.1 R10.1
VCCBATT: MC2.6
VIO2: J4.39 J5.39 MC2.2 MC2.4
VREF2: MC2.1
I2C_SCL: J4.1 J5.1 ; port SZG_I2C.SCL
I2C_SDA: J4.3 J5.3 ; port SZG_I2C.SDA
M2_ALERT_B: MC2.62 ; port M2_Control.ALERT#
M2_CLKREQ_B: MC2.63 ; port M2_Control.CLKREQ#
M2_DEVSLP: MC2.59 ; port M2_Control.DEVSLP
M2_LED_1_B: MC2.60 ; port M2_Control.LED_1#
M2_PEDET: MC2.64 ; port M2_Control.PEDET
M2_PERST_B: MC2.61 ; port M2_Control.PERST#
M2_PEWAKE_B: MC2.65 ; port M2_Control.PEWAKE#
M2_SMB_CLK: MC2.57 ; port M2_Control.SMB_CLK
M2_SMB_DATA: MC2.55 ; port M2_Control.SMB_DATA
M2_SUSCLK: MC2.66 ; port M2_Control.SUSCLK
M2_THREESTATE_N_IO: MC2.177 ; port M2_THREESTATE_N_IO
MC2A_1: MC2.3 MC2A.1
MC2A_2: MC2.5 MC2A.2
MC2A_3: MC2.7 MC2A.3
MC2A_4: MC2.9 MC2A.4
MC2A_5: MC2.8 MC2A.5
MC2A_6: MC2.10 MC2A.6
MC2A_7: MC2.11 MC2A.7
MC2A_8: MC2.13 MC2A.8
MC2A_9: MC2.12 MC2A.9
MC2A_10: MC2.14 MC2A.10
MC2A_11: MC2.15 MC2A.11
MC2A_12: MC2.17 MC2A.12
MC2A_13: MC2.16 MC2A.13
MC2A_14: MC2.18 MC2A.14
MC2A_15: MC2.19 MC2A.15
MC2A_16: MC2.21 MC2A.16
MC2A_17: MC2.20 MC2A.17
MC2A_18: MC2.22 MC2A.18
MC2A_19: MC2.67 MC2A.19
MC2A_20: MC2.69 MC2A.20
MC2A_21: MC2.68 MC2A.21
MC2A_22: MC2.70 MC2A.22
MC2A_23: MC2.71 MC2A.23
MC2A_24: MC2.73 MC2A.24
MC2A_25: MC2.72 MC2A.25
MC2A_26: MC2.74 MC2A.26
MC2A_27: MC2.75 MC2A.27
MC2A_28: MC2.77 MC2A.28
MC2A_29: MC2.76 MC2A.29
MC2A_30: MC2.78 MC2A.30
MC2A_31: MC2.111 MC2A.31
MC2A_32: MC2.113 MC2A.32
MC2A_33: MC2.112 MC2A.33
MC2A_34: MC2.114 MC2A.34
MC2A_35: MC2.115 MC2A.35
MC2A_36: MC2.117 MC2A.36
MC2A_37: MC2.116 MC2A.37
MC2A_38: MC2.118 MC2A.38
MC2A_39: MC2.119 MC2A.39
MC2A_40: MC2.120 MC2A.40
MC2B_1: MC2.137 MC2B.1
MC2B_2: MC2.138 MC2B.2
MC2B_3: MC2.139 MC2B.3
MC2B_4: MC2.140 MC2B.4
MC2B_5: MC2.141 MC2B.5
MC2B_6: MC2.142 MC2B.6
MC2B_7: MC2.143 MC2B.7
MC2B_8: MC2.144 MC2B.8
MC2B_9: MC2.145 MC2B.9
MC2B_10: MC2.146 MC2B.10
MC2B_11: MC2.147 MC2B.11
MC2B_12: MC2.148 MC2B.12
MC2B_13: MC2.149 MC2B.13
MC2B_14: MC2.150 MC2B.14
MC2B_15: MC2.151 MC2B.15
MC2B_16: MC2.152 MC2B.16
MC2B_17: MC2.153 MC2B.17
MC2B_18: MC2.154 MC2B.18
MC2B_19: MC2.155 MC2B.19
MC2B_20: MC2.156 MC2B.20
MC2B_21: MC2.157 MC2B.21
MC2B_22: MC2.158 MC2B.22
MC2B_23: MC2.159 MC2B.23
MC2B_24: MC2.160 MC2B.24
MC2B_25: MC2.161 MC2B.25
MC2B_26: MC2.162 MC2B.26
MC2B_27: MC2.163 MC2B.27
MC2B_28: MC2.164 MC2B.28
MC2B_29: MC2.165 MC2B.29
MC2B_30: MC2.166 MC2B.30
MC2B_31: MC2.167 MC2B.31
MC2B_32: MC2.168 MC2B.32
MC2B_33: MC2.169 MC2B.33
MC2B_34: MC2.170 MC2B.34
MC2B_35: MC2.171 MC2B.35
MC2B_36: MC2.172 MC2B.36
MC2B_37: MC2.173 MC2B.37
MC2B_38: MC2.174 MC2B.38
MC2B_39: MC2.175 MC2B.39
MC2B_40: MC2.176 MC2B.40
PORTA_C2P_CLKN: J5.36 MC2.109
PORTA_C2P_CLKP: J5.34 MC2.107
PORTA_P2C_CLKN: J5.35 MC2.86
PORTA_P2C_CLKP: J5.33 MC2.84
PORTA_S0_D0P: J5.5 MC2.79
PORTA_S1_D1P: J5.6 MC2.80
PORTA_S2_D0N: J5.7 MC2.81
PORTA_S3_D1N: J5.8 MC2.82
PORTA_S4_D2P: J5.9 MC2.83
PORTA_S5_D3P: J5.10 MC2.96
PORTA_S6_D2N: J5.11 MC2.85
PORTA_S7_D3N: J5.12 MC2.98
PORTA_S8_D4P: J5.13 MC2.92
PORTA_S9_D5P: J5.14 MC2.100
PORTA_S10_D4N: J5.15 MC2.94
PORTA_S11_D5N: J5.16 MC2.102
PORTA_S12_D6P: J5.17 MC2.88
PORTA_S13_D7P: J5.18 MC2.108
PORTA_S14_D6N: J5.19 MC2.90
PORTA_S15_D7N: J5.20 MC2.110
PORTA_S16: J5.21 MC2.106
PORTA_S17: J5.22 MC2.89
PORTA_S18: J5.23 MC2.104
PORTA_S19: J5.24 MC2.87
PORTA_S20: J5.25 MC2.99
PORTA_S21: J5.26 MC2.93
PORTA_S22: J5.27 MC2.101
PORTA_S23: J5.28 MC2.91
PORTA_S24: J5.29 MC2.103
PORTA_S25: J5.30 MC2.97
PORTA_S26: J5.31 MC2.105
PORTA_S27: J5.32 MC2.95
PORTB_C2P_CLKN: J4.36 MC2.40
PORTB_C2P_CLKP: J4.34 MC2.38
PORTB_P2C_CLKN: J4.35 MC2.47
PORTB_P2C_CLKP: J4.33 MC2.45
PORTB_S0_D0P: J4.5 MC2.31
PORTB_S1_D1P: J4.6 MC2.23
PORTB_S2_D0N: J4.7 MC2.33
PORTB_S3_D1N: J4.8 MC2.25
PORTB_S4_D2P: J4.9 MC2.41
PORTB_S5_D3P: J4.10 MC2.27
PORTB_S6_D2N: J4.11 MC2.43
PORTB_S7_D3N: J4.12 MC2.29
PORTB_S8_D4P: J4.13 MC2.32
PORTB_S9_D5P: J4.14 MC2.37
PORTB_S10_D4N: J4.15 MC2.34
PORTB_S11_D5N: J4.16 MC2.39
PORTB_S12_D6P: J4.17 MC2.42
PORTB_S13_D7P: J4.18 MC2.28
PORTB_S14_D6N: J4.19 MC2.44
PORTB_S15_D7N: J4.20 MC2.30
PORTB_S16: J4.21 MC2.58
PORTB_S17: J4.22 MC2.52
PORTB_S18: J4.23 MC2.56
PORTB_S19: J4.24 MC2.36
PORTB_S20: J4.25 MC2.35
PORTB_S21: J4.26 MC2.48
PORTB_S22: J4.27 MC2.49
PORTB_S23: J4.28 MC2.46
PORTB_S24: J4.29 MC2.51
PORTB_S25: J4.30 MC2.54
PORTB_S26: J4.31 MC2.53
PORTB_S27: J4.32 MC2.50
QSFP_1_INT_B: MC2.129 ; port QSFP1_Control.IntL
QSFP_1_LP_MODE: MC2.125 ; port QSFP1_Control.LPMode
QSFP_1_MODPRS_B: MC2.126 ; port QSFP1_Control.ModPrsL
QSFP_1_MODSEL_B: MC2.122 ; port QSFP1_Control.ModselL
QSFP_1_RESET_B: MC2.124 ; port QSFP1_Control.ResetL
QSFP_1_SCL: MC2.123 ; port QSFP1_Control.SCL
QSFP_1_SDA: MC2.121 ; port QSFP1_Control.SDA
QSFP_2_INT_B: MC2.127 ; port QSFP2_Control.IntL
QSFP_2_LP_MODE: MC2.128 ; port QSFP2_Control.LPMode
QSFP_2_MODPRS_B: MC2.134 ; port QSFP2_Control.ModPrsL
QSFP_2_MODSEL_B: MC2.130 ; port QSFP2_Control.ModselL
QSFP_2_RESET_B: MC2.132 ; port QSFP2_Control.ResetL
QSFP_2_SCL: MC2.131 ; port QSFP2_Control.SCL
QSFP_2_SDA: MC2.133 ; port QSFP2_Control.SDA
QSFP_THREESTATE_N_IO: MC2.179 ; port QSFP_THREESTATE_N_IO
NetJ4_4: J4.4 R10.2
NetJ5_4: J5.4 R9.2

Not connected (* = marked no-connect by the designer): J4 37* 38*; J5 37* 38*; MC2 24* 26* 135* 136* 178* 180*

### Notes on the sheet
- Mezzanine Connector MC2
- SYZYGY PORT A (VIO2)
- Address 0x38
- Address 0x39
- SYZYGY PORT B (VIO2)
- 2mm Headers
- B44_L2P
  B44_L2N
  B44_L7P
  B44_L7N
  B44_L9P
  B44_L9N
  B44_L4P
  B44_L4N
  B44_L10P
  B44_L10N
  B45_L22P
  B45_L22N
  B45_L20P
  B45_L20N
  B45_L18P
  B45_L18N
  B45_T1U_N12
  B45_L24P
  B45_L24N
  B45_L21P
  B45_L21N
  B45_L12P
  B45_L12N
  B45_L19P
  B45_L19N
  B45_L10P
  B45_L10N
  B45_L8P
  B45_L8N
  B45_L16P
  B45_L16N
  B45_T3U_N12
  B45_L4P
  B45_L4N
  B45_L11P
  B45_L11N
  B24_L2P
  B24_L2N
  B24_L10P
  B24_L10N
  B24_L12P
  B24_L12N
  B24_L14P
  B24_L14N
  B24_L4P
  B24_L4N
  B24_L6P
  B24_L6N
  B24_L8P
  B24_L8N
  B24_L24P
  B24_L24N
  B24_L9P
  B24_L9N
  B24_L19P
  B24_L19N
  B24_L21P
  B24_L21N
  B24_T1U_N12
  B24_L5P
  B24_L5N
  B24_T2U_N12
  B25_L15P
  B25_L15N
  B25_L1P
  B25_L1N
  B25_L2P
  B25_L2N
  B25_L21P
  B25_L21N
  B25_L23P
  B25_L23N
  B25_L19P
  B25_L19N
  B25_T2U_N12
  B25_L9P
  B25_L9N
  B25_L8P
  B25_L8N
  B25_L20P
  B25_L20N
  B25_L16P
  B25_L16N
  B25_L18P
  B25_L18N
  B25_T1U_N12
  B25_L22P
  B25_L22N
  B25_T3U_N12
- B44_L3P
  B44_L3N
  B44_L8P
  B44_L8N
  B44_L6P
  B44_L6N
  B44_L5P
  B44_L5N
  B44_L1P
  B44_L1N
  B45_L23P
  B45_L23N
  B45_L15P
  B45_L15N
  B45_T0U_N12
  B45_L6P
  B45_L6N
  B45_L2P
  B45_L2N
  B45_L7P
  B45_L7N
  B45_L1P
  B45_L1N
  B45_L17P
  B45_L17N
  B45_L5P
  B45_L5N
  B45_L9P
  B45_L9N
  B45_T2U_N12
  B45_L14P
  B45_L14N
  B45_L13P
  B45_L13N
  B45_L3P
  B45_L3N
  B24_L13P
  B24_L13N
  B24_L11P
  B24_L11N
  B24_L15P
  B24_L15N
  B24_L7P
  B24_L7N
  B24_L3P
  B24_L3N
  B24_L18P
  B24_L18N
  B24_L22P
  B24_L22N
  B24_L23P
  B24_L23N
  B24_L17P
  B24_L17N
  B24_L20P
  B24_L20N
  B24_T0U_N12
  B24_L16P
  B24_L16N
  B24_L1P
  B24_L1N
  B24_T3U_N12
  B25_L5P
  B25_L5N
  B25_L3P
  B25_L3N
  B25_L6P
  B25_L6N
  B25_L17P
  B25_L17N
  B25_L13P
  B25_L13N
  B25_L4P
  B25_L4N
  B25_T0U_N12
  B25_L7P
  B25_L7N
  B25_L11P
  B25_L11N
  B25_L14P
  B25_L14N
  B25_L10P
  B25_L10N
  B25_L24P
  B25_L24N
  B25_L12P
  B25_L12N
- Title
- Size:
- Date:
- C
- Number:
- Time:
- Revision:
- Sheet
- of

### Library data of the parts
J4 J5 = 001604: 0.8mm hi-speed, high-density header (male); Manufacturer: Samtec; partnumber: 001604; Description 2: 40-pin, ground protection in middle; x_lifecycle_status: Production
MC2 = 000876: 0.5mm Double Row High Speed Socket Assembly; Partnumber: 000876; manufacturer: Samtec; id: 17471; inventory_price: 8.87
MC2A MC2B = 000583: Partnumber: 000583; manufacturer: Molex; id: 9990; inventory_price: 1.03
MC2C MC2D = 001334: PartNumber: 001334; manufacturer: 3M; manufacturer_pn: 951120-8622-AR; id: 98023; inventory_price: 0.924
R9 = Resistor: Thick-film resistor; manufacturer: Yageo; partnumber: 001908; ValueFloat: 8870.0
R10 = Resistor: Thick-film resistor; manufacturer: Yageo; partnumber: 001909; ValueFloat: 6980.0

## Sheet MC1.SchDoc: BRK8350 - Mezzanine Connector MC1
size C; Author: Casey Smith; Organization: Opal Kelly; Address1: 13500 SW 72nd Ave STE 100; Address2: Portland, OR 97223; Address3: 217.391.3724; Address4: http://www.opalkelly.com; DocumentNumber: 2; Revision: 1; SheetNumber: 2; SheetTotal: 7
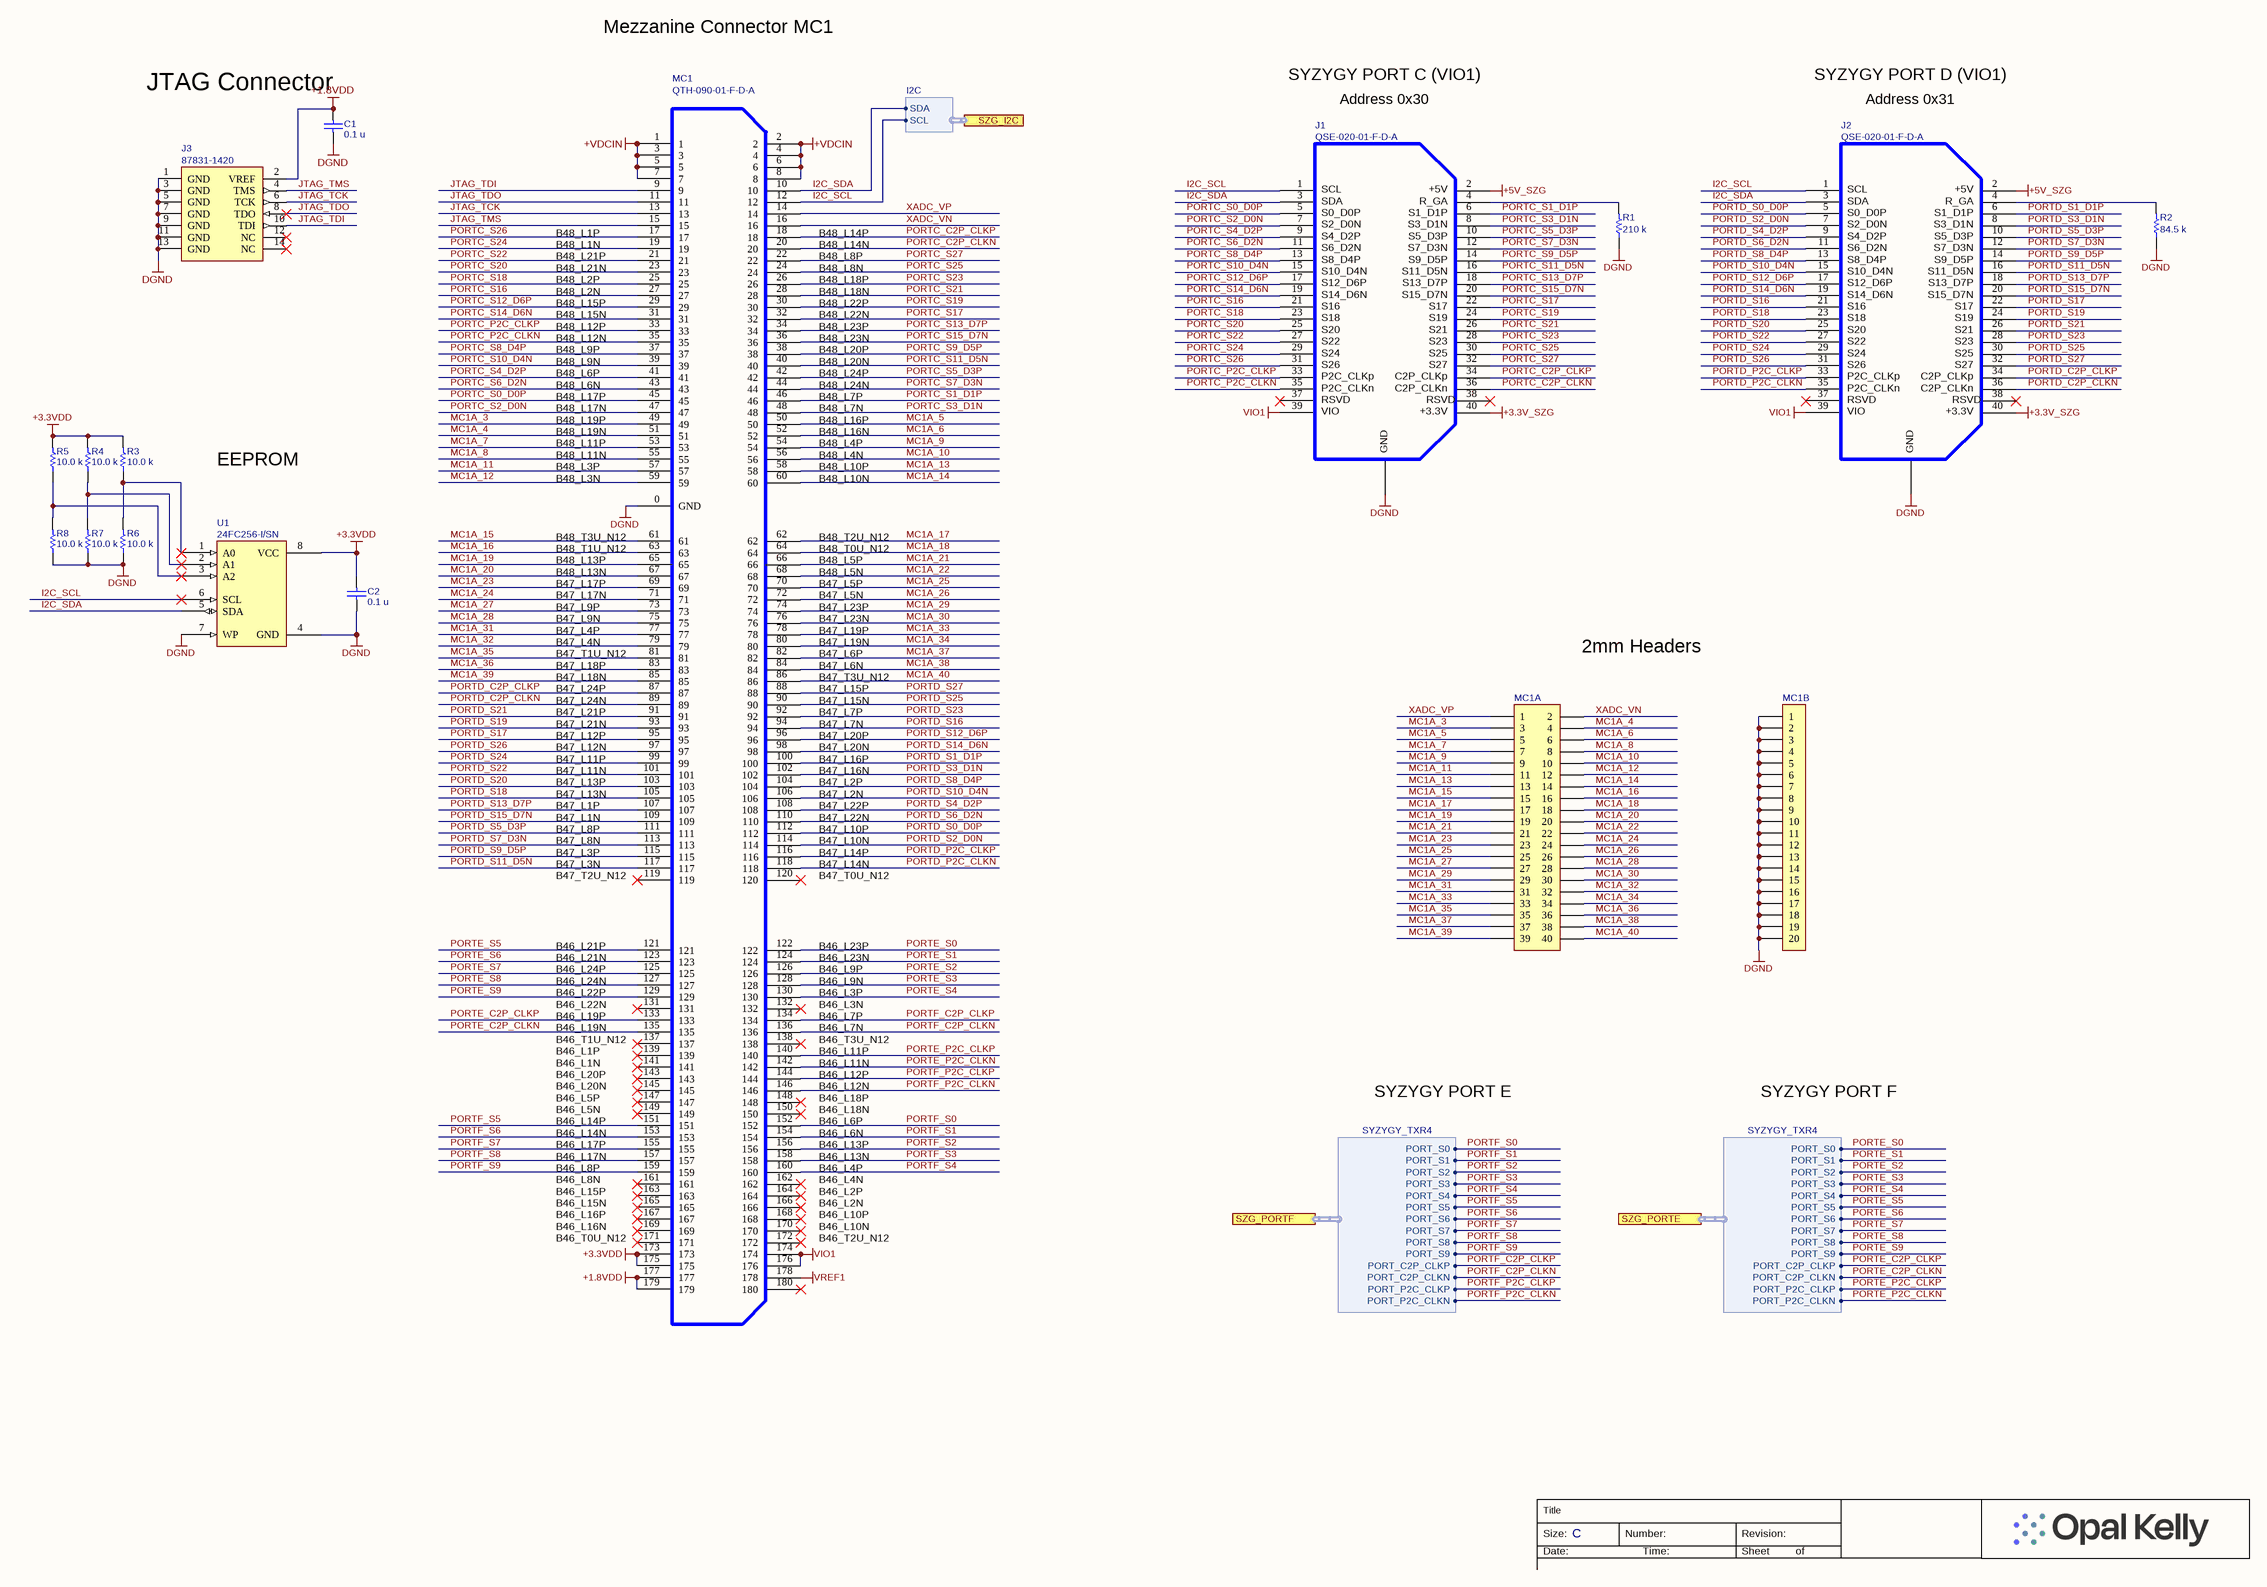
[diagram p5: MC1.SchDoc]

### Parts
C1  value 0.1 u  [CAPC1005X06A]  (hidden comment: SM-0402, 10%, 10v)
C2  value 0.1 u  [CAPC1005X06A]  (hidden comment: SM-0402, 10%, 10v)
J1  QSE-020-01-F-D-A  [QSE-020-01-X-D-A-L-SYZYGY]
J2  QSE-020-01-F-D-A  [QSE-020-01-X-D-A-L-SYZYGY]
J3  87831-1420  [XILINX-JTAG]
MC1  QTH-090-01-F-D-A  [QTH-090-01-X-D]
MC1A  0877584016  [HDR2X20-2MM]  (value not drawn)
MC1B  Header, 20-Pin, Single Row  [HDR1X20-2MM]  (value not drawn)
R1  value 210 k  [RESC1005X06A]  (hidden comment: CRCW0402210KFKED)
R2  value 84.5 k  [RESC1005X06A]  (hidden comment: CRCW040284K5FKED)
R3  value 10.0 k  [RESC1005X06A]  (hidden comment: SM-0402, 1%, 1/16W)
R4  value 10.0 k  [RESC1005X06A]  (hidden comment: SM-0402, 1%, 1/16W)
R5  value 10.0 k  [RESC1005X06A]  (hidden comment: SM-0402, 1%, 1/16W)
R6  value 10.0 k  [RESC1005X06A]  (hidden comment: SM-0402, 1%, 1/16W)
R7  value 10.0 k  [RESC1005X06A]  (hidden comment: SM-0402, 1%, 1/16W)
R8  value 10.0 k  [RESC1005X06A]  (hidden comment: SM-0402, 1%, 1/16W)
U1  24FC256-I/SN  [SO-G8]

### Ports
SZG_I2C (harness I2C), SZG_PORTE (harness SYZYGY_TXR4), SZG_PORTF (harness SYZYGY_TXR4)

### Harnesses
I2C: SCL, SDA
SYZYGY_TXR4: PORT_S0, PORT_S1, PORT_S2, PORT_S3, PORT_S4, PORT_S5, PORT_S6, PORT_S7, PORT_S8, PORT_S9, PORT_C2P_CLKP, PORT_C2P_CLKN, PORT_P2C_CLKP, PORT_P2C_CLKN

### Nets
+1.8VDD: C1.2 J3.2(VREF) MC1.177 MC1.179
+3.3V_SZG: J1.40 J2.40
+3.3VDD: C2.2 MC1.173 MC1.175 R3.2 R4.2 R5.2 U1.8(VCC)
+5V_SZG: J1.2 J2.2
+VDCIN: MC1.1 MC1.2 MC1.3 MC1.4 MC1.5 MC1.6 MC1.7 MC1.8
DGND: C1.1 C2.1 J1.0 J2.0 J3.1(GND) J3.3(GND) J3.5(GND) J3.7(GND) J3.9(GND) J3.11(GND) J3.13(GND) MC1.0(GND) MC1B.1 MC1B.2 MC1B.3 MC1B.4 MC1B.5 MC1B.6 MC1B.7 MC1B.8 MC1B.9 MC1B.10 MC1B.11 MC1B.12 MC1B.13 MC1B.14 MC1B.15 MC1B.16 MC1B.17 MC1B.18 MC1B.19 MC1B.20 R1.1 R2.1 R6.1 R7.1 R8.1 U1.4(GND) U1.7(WP)
VIO1: J1.39 J2.39 MC1.174 MC1.176
VREF1: MC1.178
I2C_SCL: J1.1 J2.1 MC1.12 U1.6(SCL) ; port SZG_I2C.SCL
I2C_SDA: J1.3 J2.3 MC1.10 U1.5(SDA) ; port SZG_I2C.SDA
JTAG_TCK: J3.6(TCK) MC1.13
JTAG_TDI: J3.10(TDI) MC1.9
JTAG_TDO: J3.8(TDO) MC1.11
JTAG_TMS: J3.4(TMS) MC1.15
MC1A_3: MC1.49 MC1A.3
MC1A_4: MC1.51 MC1A.4
MC1A_5: MC1.50 MC1A.5
MC1A_6: MC1.52 MC1A.6
MC1A_7: MC1.53 MC1A.7
MC1A_8: MC1.55 MC1A.8
MC1A_9: MC1.54 MC1A.9
MC1A_10: MC1.56 MC1A.10
MC1A_11: MC1.57 MC1A.11
MC1A_12: MC1.59 MC1A.12
MC1A_13: MC1.58 MC1A.13
MC1A_14: MC1.60 MC1A.14
MC1A_15: MC1.61 MC1A.15
MC1A_16: MC1.63 MC1A.16
MC1A_17: MC1.62 MC1A.17
MC1A_18: MC1.64 MC1A.18
MC1A_19: MC1.65 MC1A.19
MC1A_20: MC1.67 MC1A.20
MC1A_21: MC1.66 MC1A.21
MC1A_22: MC1.68 MC1A.22
MC1A_23: MC1.69 MC1A.23
MC1A_24: MC1.71 MC1A.24
MC1A_25: MC1.70 MC1A.25
MC1A_26: MC1.72 MC1A.26
MC1A_27: MC1.73 MC1A.27
MC1A_28: MC1.75 MC1A.28
MC1A_29: MC1.74 MC1A.29
MC1A_30: MC1.76 MC1A.30
MC1A_31: MC1.77 MC1A.31
MC1A_32: MC1.79 MC1A.32
MC1A_33: MC1.78 MC1A.33
MC1A_34: MC1.80 MC1A.34
MC1A_35: MC1.81 MC1A.35
MC1A_36: MC1.83 MC1A.36
MC1A_37: MC1.82 MC1A.37
MC1A_38: MC1.84 MC1A.38
MC1A_39: MC1.85 MC1A.39
MC1A_40: MC1.86 MC1A.40
PORTC_C2P_CLKN: J1.36 MC1.20
PORTC_C2P_CLKP: J1.34 MC1.18
PORTC_P2C_CLKN: J1.35 MC1.35
PORTC_P2C_CLKP: J1.33 MC1.33
PORTC_S0_D0P: J1.5 MC1.45
PORTC_S1_D1P: J1.6 MC1.46
PORTC_S2_D0N: J1.7 MC1.47
PORTC_S3_D1N: J1.8 MC1.48
PORTC_S4_D2P: J1.9 MC1.41
PORTC_S5_D3P: J1.10 MC1.42
PORTC_S6_D2N: J1.11 MC1.43
PORTC_S7_D3N: J1.12 MC1.44
PORTC_S8_D4P: J1.13 MC1.37
PORTC_S9_D5P: J1.14 MC1.38
PORTC_S10_D4N: J1.15 MC1.39
PORTC_S11_D5N: J1.16 MC1.40
PORTC_S12_D6P: J1.17 MC1.29
PORTC_S13_D7P: J1.18 MC1.34
PORTC_S14_D6N: J1.19 MC1.31
PORTC_S15_D7N: J1.20 MC1.36
PORTC_S16: J1.21 MC1.27
PORTC_S17: J1.22 MC1.32
PORTC_S18: J1.23 MC1.25
PORTC_S19: J1.24 MC1.30
PORTC_S20: J1.25 MC1.23
PORTC_S21: J1.26 MC1.28
PORTC_S22: J1.27 MC1.21
PORTC_S23: J1.28 MC1.26
PORTC_S24: J1.29 MC1.19
PORTC_S25: J1.30 MC1.24
PORTC_S26: J1.31 MC1.17
PORTC_S27: J1.32 MC1.22
PORTD_C2P_CLKN: J2.36 MC1.89
PORTD_C2P_CLKP: J2.34 MC1.87
PORTD_P2C_CLKN: J2.35 MC1.118
PORTD_P2C_CLKP: J2.33 MC1.116
PORTD_S0_D0P: J2.5 MC1.112
PORTD_S1_D1P: J2.6 MC1.100
PORTD_S2_D0N: J2.7 MC1.114
PORTD_S3_D1N: J2.8 MC1.102
PORTD_S4_D2P: J2.9 MC1.108
PORTD_S5_D3P: J2.10 MC1.111
PORTD_S6_D2N: J2.11 MC1.110
PORTD_S7_D3N: J2.12 MC1.113
PORTD_S8_D4P: J2.13 MC1.104
PORTD_S9_D5P: J2.14 MC1.115
PORTD_S10_D4N: J2.15 MC1.106
PORTD_S11_D5N: J2.16 MC1.117
PORTD_S12_D6P: J2.17 MC1.96
PORTD_S13_D7P: J2.18 MC1.107
PORTD_S14_D6N: J2.19 MC1.98
PORTD_S15_D7N: J2.20 MC1.109
PORTD_S16: J2.21 MC1.94
PORTD_S17: J2.22 MC1.95
PORTD_S18: J2.23 MC1.105
PORTD_S19: J2.24 MC1.93
PORTD_S20: J2.25 MC1.103
PORTD_S21: J2.26 MC1.91
PORTD_S22: J2.27 MC1.101
PORTD_S23: J2.28 MC1.92
PORTD_S24: J2.29 MC1.99
PORTD_S25: J2.30 MC1.90
PORTD_S26: J2.31 MC1.97
PORTD_S27: J2.32 MC1.88
PORTE_C2P_CLKN: MC1.135 ; port SZG_PORTE.PORT_C2P_CLKN
PORTE_C2P_CLKP: MC1.133 ; port SZG_PORTE.PORT_C2P_CLKP
PORTE_P2C_CLKN: MC1.142 ; port SZG_PORTE.PORT_P2C_CLKN
PORTE_P2C_CLKP: MC1.140 ; port SZG_PORTE.PORT_P2C_CLKP
PORTE_S0: MC1.122 ; port SZG_PORTE.PORT_S0
PORTE_S1: MC1.124 ; port SZG_PORTE.PORT_S1
PORTE_S2: MC1.126 ; port SZG_PORTE.PORT_S2
PORTE_S3: MC1.128 ; port SZG_PORTE.PORT_S3
PORTE_S4: MC1.130 ; port SZG_PORTE.PORT_S4
PORTE_S5: MC1.121 ; port SZG_PORTE.PORT_S5
PORTE_S6: MC1.123 ; port SZG_PORTE.PORT_S6
PORTE_S7: MC1.125 ; port SZG_PORTE.PORT_S7
PORTE_S8: MC1.127 ; port SZG_PORTE.PORT_S8
PORTE_S9: MC1.129 ; port SZG_PORTE.PORT_S9
PORTF_C2P_CLKN: MC1.136 ; port SZG_PORTF.PORT_C2P_CLKN
PORTF_C2P_CLKP: MC1.134 ; port SZG_PORTF.PORT_C2P_CLKP
PORTF_P2C_CLKN: MC1.146 ; port SZG_PORTF.PORT_P2C_CLKN
PORTF_P2C_CLKP: MC1.144 ; port SZG_PORTF.PORT_P2C_CLKP
PORTF_S0: MC1.152 ; port SZG_PORTF.PORT_S0
PORTF_S1: MC1.154 ; port SZG_PORTF.PORT_S1
PORTF_S2: MC1.156 ; port SZG_PORTF.PORT_S2
PORTF_S3: MC1.158 ; port SZG_PORTF.PORT_S3
PORTF_S4: MC1.160 ; port SZG_PORTF.PORT_S4
PORTF_S5: MC1.151 ; port SZG_PORTF.PORT_S5
PORTF_S6: MC1.153 ; port SZG_PORTF.PORT_S6
PORTF_S7: MC1.155 ; port SZG_PORTF.PORT_S7
PORTF_S8: MC1.157 ; port SZG_PORTF.PORT_S8
PORTF_S9: MC1.159 ; port SZG_PORTF.PORT_S9
XADC_VN: MC1.16 MC1A.2
XADC_VP: MC1.14 MC1A.1
NetJ1_4: J1.4 R1.2
NetJ2_4: J2.4 R2.2
NetR3_1: R3.1 R6.2 U1.1(A0)
NetR4_1: R4.1 R7.2 U1.2(A1)
NetR5_1: R5.1 R8.2 U1.3(A2)

Not connected (* = marked no-connect by the designer): J1 37* 38*; J2 37* 38*; J3 12(NC)* 14(NC)*; MC1 119* 120* 131* 132* 137* 138* 139* 141* 143* 145* 147* 148* 149* 150* 161* 162* 163* 164* 165* 166* 167* 168* 169* 170* 171* 172* 180*

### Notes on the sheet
- Mezzanine Connector MC1
- (near C1) JTAG Connector
- SYZYGY PORT C (VIO1)
- Address 0x30
- SYZYGY PORT D (VIO1)
- Address 0x31
- EEPROM
- 2mm Headers
- SYZYGY PORT E
- SYZYGY PORT F
- B48_L1P
  B48_L1N
  B48_L21P
  B48_L21N
  B48_L2P
  B48_L2N
  B48_L15P
  B48_L15N
  B48_L12P
  B48_L12N
  B48_L9P
  B48_L9N
  B48_L6P
  B48_L6N
  B48_L17P
  B48_L17N
  B48_L19P
  B48_L19N
  B48_L11P
  B48_L11N
  B48_L3P
  B48_L3N
  B48_T3U_N12
  B48_T1U_N12
  B48_L13P
  B48_L13N
  B47_L17P
  B47_L17N
  B47_L9P
  B47_L9N
  B47_L4P
  B47_L4N
  B47_T1U_N12
  B47_L18P
  B47_L18N
  B47_L24P
  B47_L24N
  B47_L21P
  B47_L21N
  B47_L12P
  B47_L12N
  B47_L11P
  B47_L11N
  B47_L13P
  B47_L13N
  B47_L1P
  B47_L1N
  B47_L8P
  B47_L8N
  B47_L3P
  B47_L3N
  B47_T2U_N12
  B46_L21P
  B46_L21N
  B46_L24P
  B46_L24N
  B46_L22P
  B46_L22N
  B46_L19P
  B46_L19N
  B46_T1U_N12
  B46_L1P
  B46_L1N
  B46_L20P
  B46_L20N
  B46_L5P
  B46_L5N
  B46_L14P
  B46_L14N
  B46_L17P
  B46_L17N
  B46_L8P
  B46_L8N
  B46_L15P
  B46_L15N
  B46_L16P
  B46_L16N
  B46_T0U_N12
- B48_L14P
  B48_L14N
  B48_L8P
  B48_L8N
  B48_L18P
  B48_L18N
  B48_L22P
  B48_L22N
  B48_L23P
  B48_L23N
  B48_L20P
  B48_L20N
  B48_L24P
  B48_L24N
  B48_L7P
  B48_L7N
  B48_L16P
  B48_L16N
  B48_L4P
  B48_L4N
  B48_L10P
  B48_L10N
  B48_T2U_N12
  B48_T0U_N12
  B48_L5P
  B48_L5N
  B47_L5P
  B47_L5N
  B47_L23P
  B47_L23N
  B47_L19P
  B47_L19N
  B47_L6P
  B47_L6N
  B47_T3U_N12
  B47_L15P
  B47_L15N
  B47_L7P
  B47_L7N
  B47_L20P
  B47_L20N
  B47_L16P
  B47_L16N
  B47_L2P
  B47_L2N
  B47_L22P
  B47_L22N
  B47_L10P
  B47_L10N
  B47_L14P
  B47_L14N
  B47_T0U_N12
  B46_L23P
  B46_L23N
  B46_L9P
  B46_L9N
  B46_L3P
  B46_L3N
  B46_L7P
  B46_L7N
  B46_T3U_N12
  B46_L11P
  B46_L11N
  B46_L12P
  B46_L12N
  B46_L18P
  B46_L18N
  B46_L6P
  B46_L6N
  B46_L13P
  B46_L13N
  B46_L4P
  B46_L4N
  B46_L2P
  B46_L2N
  B46_L10P
  B46_L10N
  B46_T2U_N12
- Title
- Size:
- Date:
- C
- Number:
- Time:
- Revision:
- Sheet
- of

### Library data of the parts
C1 = 000070: as C90 on sheet Transceiver-QSFP
C2 = 000070: Partnumber: 000070; manufacturer: Kemet; manufacturer_pn: C0402C104K8PACTU; ValueFloat: 1E-7; id: 750; inventory_price: 0.0023; reorder_quantity: 70000; x_max_operating_temp: 85; x_min_operating_temp: -55; x_tolerance: 10
J1 J2 = 001604: as J4 on sheet MC2
J3 = 000541: 2mm header, shrouded; Manufacturer: Molex; partnumber: 000541; Description 2: Dual-row, 14-pos, Xilinx JTAG compatible
MC1 = 000876: as MC2 on sheet MC2
MC1A = 000583: as MC2A on sheet MC2
MC1B = 001334: as MC2C on sheet MC2
R1 = 001549: Thick-film resistor; Manufacturer: Vishay; partnumber: 001549; Description 2: SM-0402, 1%, 1/16W; ValueFloat: 210000; Tolerance (%): 1; x_lifecycle_status: Production
R2 = 001550: Thick-film resistor; Manufacturer: Vishay; partnumber: 001550; Description 2: SM-0402, 1%, 1/16W; ValueFloat: 84500; Tolerance (%): 1; x_lifecycle_status: Production
R3-R8 = 001521: Partnumber: 001521; manufacturer: Vishay; manufacturer_pn: CRCW040210K0FKED; ValueFloat: 10000; id: 154248; inventory_price: 0.0016; x_tolerance: 1
U1 = 000842: Partnumber: 000842; manufacturer: Microchip; id: 14766; inventory_price: 0.39; reorder_quantity: 600

## Sheet Power.SchDoc: BRK8350 - Power
size C; Organization: Opal Kelly; Address1: 13500 SW 72nd Ave STE 100; Address3: Portland, OR  97223; Address4: http://www.opalkelly.com; DocumentNumber: 7; Revision: 1; SheetNumber: 7; SheetTotal: 7; PageSetup: Record=PageOptions¦CenterHorizontal=True¦CenterVertical=True¦PrintScale=0.52¦XCorrection=1.00¦YCorrection=1.00¦PrintKind=0¦BorderSize=5000000¦LeftOffset=0¦BottomOffset=0¦Orientation=2¦PaperLength=1000¦PaperWidth=1000¦Scale=100¦PaperSource=15¦PrintQuality=600¦MediaType=1¦DitherType=10¦PaperKind=Letter¦PrintScaleMode=1
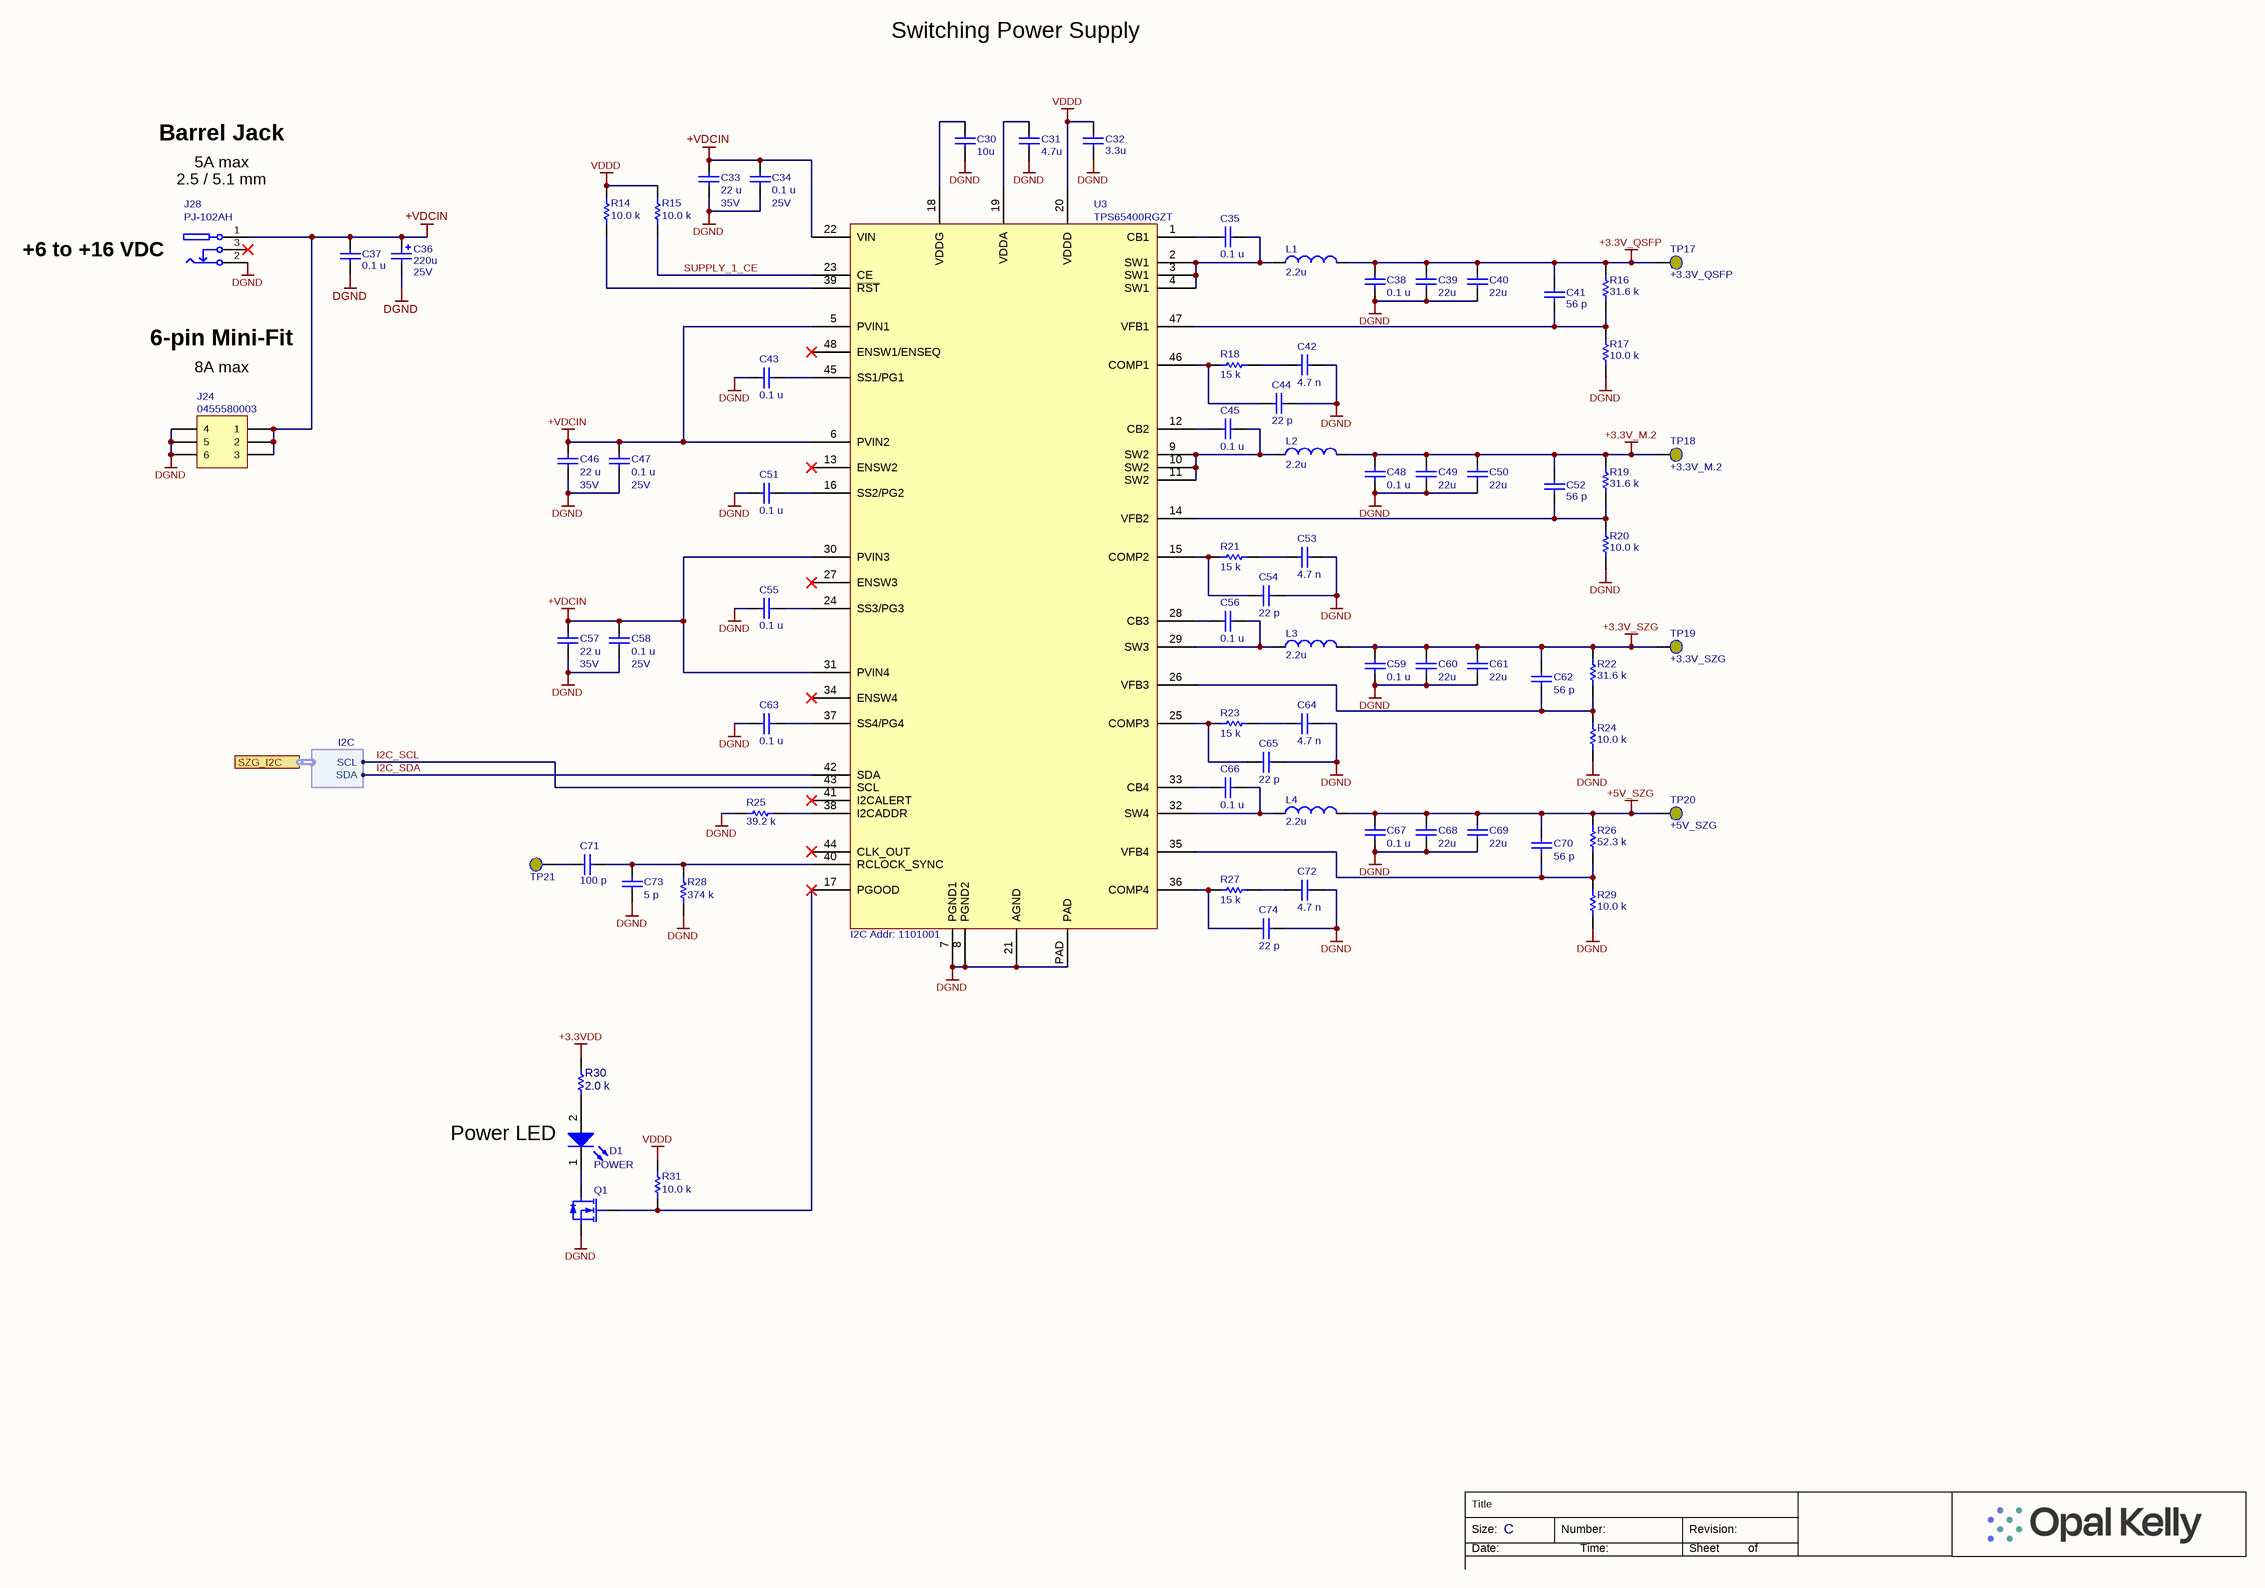
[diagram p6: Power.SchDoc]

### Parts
C30  value 10u  [CAPC1608N]  (hidden comment: LMK107BJ106MALTD)
C31  value 4.7u  [CAPC1005X06A]  (hidden comment: JMK105BBJ475MV-F)
C32  value 3.3u  [CAPC1005X06A]  (hidden comment: C1005X5R1A335K050BC)
C33  value 22 u  Voltage: 35V  [CAPC3216N]  (hidden comment: C3216X5R1V226M160AC)
C34  value 0.1 u  Voltage: 25V  [CAPC1005X06A]  (hidden comment: TMK105BJ104KV-F)
C35  value 0.1 u  [CAPC1005X06A]  (hidden comment: C0402C104K8PACTU)
C36  value 220u  Voltage: 25V  [CAPAE9083X70N]  (hidden comment: EEE-FK1E221P)
C37  value 0.1 u  [CAPC1005X06A]  (hidden comment: TMK105BJ104KV-F)
C38  value 0.1 u  [CAPC1005X06A]  (hidden comment: C0402C104K8PACTU)
C39  value 22u  [CAPC3216N]  (hidden comment: LMK316AB7226KL-TR)
C40  value 22u  [CAPC3216N]  (hidden comment: LMK316AB7226KL-TR)
C41  value 56 p  [CAPC1005X06A]  (hidden comment: SM-0402, 5%, 50v)
C42  value 4.7 n  [CAPC1005X06A]  (hidden comment: C0402C472K5RACTU)
C43  value 0.1 u  [CAPC1005X06A]  (hidden comment: C0402C104K8PACTU)
C44  value 22 p  [CAPC1005X06A]  (hidden comment: C0402C220J5GACTU)
C45  value 0.1 u  [CAPC1005X06A]  (hidden comment: C0402C104K8PACTU)
C46  value 22 u  Voltage: 35V  [CAPC3216N]  (hidden comment: C3216X5R1V226M160AC)
C47  value 0.1 u  Voltage: 25V  [CAPC1005X06A]  (hidden comment: TMK105BJ104KV-F)
C48  value 0.1 u  [CAPC1005X06A]  (hidden comment: C0402C104K8PACTU)
C49  value 22u  [CAPC3216N]  (hidden comment: LMK316AB7226KL-TR)
C50  value 22u  [CAPC3216N]  (hidden comment: LMK316AB7226KL-TR)
C51  value 0.1 u  [CAPC1005X06A]  (hidden comment: C0402C104K8PACTU)
C52  value 56 p  [CAPC1005X06A]  (hidden comment: SM-0402, 5%, 50v)
C53  value 4.7 n  [CAPC1005X06A]  (hidden comment: C0402C472K5RACTU)
C54  value 22 p  [CAPC1005X06A]  (hidden comment: C0402C220J5GACTU)
C55  value 0.1 u  [CAPC1005X06A]  (hidden comment: C0402C104K8PACTU)
C56  value 0.1 u  [CAPC1005X06A]  (hidden comment: C0402C104K8PACTU)
C57  value 22 u  Voltage: 35V  [CAPC3216N]  (hidden comment: C3216X5R1V226M160AC)
C58  value 0.1 u  Voltage: 25V  [CAPC1005X06A]  (hidden comment: TMK105BJ104KV-F)
C59  value 0.1 u  [CAPC1005X06A]  (hidden comment: C0402C104K8PACTU)
C60  value 22u  [CAPC3216N]  (hidden comment: LMK316AB7226KL-TR)
C61  value 22u  [CAPC3216N]  (hidden comment: LMK316AB7226KL-TR)
C62  value 56 p  [CAPC1005X06A]  (hidden comment: C0402C560J5GACTU)
C63  value 0.1 u  [CAPC1005X06A]  (hidden comment: C0402C104K8PACTU)
C64  value 4.7 n  [CAPC1005X06A]  (hidden comment: C0402C472K5RACTU)
C65  value 22 p  [CAPC1005X06A]  (hidden comment: C0402C220J5GACTU)
C66  value 0.1 u  [CAPC1005X06A]  (hidden comment: C0402C104K8PACTU)
C67  value 0.1 u  [CAPC1005X06A]  (hidden comment: C0402C104K8PACTU)
C68  value 22u  [CAPC3216N]  (hidden comment: LMK316AB7226KL-TR)
C69  value 22u  [CAPC3216N]  (hidden comment: LMK316AB7226KL-TR)
C70  value 56 p  [CAPC1005X06A]  (hidden comment: C0402C560J5GACTU)
C71  value 100 p  [CAPC1005X06A]  (hidden comment: SM-0402, 5%, 50V, NP0)
C72  value 4.7 n  [CAPC1005X06A]  (hidden comment: C0402C472K5RACTU)
C73  value 5 p  [CAPC1005X06A]  (hidden comment: GJM1555C1H5R0CB01D)
C74  value 22 p  [CAPC1005X06A]  (hidden comment: C0402C220J5GACTU)
D1  POWER  [CD1608-0603-PIN1-CATHODE]
J24  0455580003  [0455580003]
J28  PJ-102AH  [CUI-PJ102A]
L1  value 2.2u  [XAL60XX]  (hidden comment: XAL6030-222MEB)
L2  value 2.2u  [XAL60XX]  (hidden comment: XAL6030-222MEB)
L3  value 2.2u  [VLS4012CX]  (hidden comment: VLS4012CX-2R2M-1)
L4  value 2.2u  [VLS4012CX]  (hidden comment: VLS4012CX-2R2M-1)
Q1  2.2A, 30V  [SOT23-95P240X110]  (value not drawn)
R14  value 10.0 k  [RESC1005X06A]  (hidden comment: CRCW040210K0FKED)
R15  value 10.0 k  [RESC1005X06A]  (hidden comment: CRCW040210K0FKED)
R16  value 31.6 k  [RESC1005X06A]  (hidden comment: SM-0402, 1%, 1/16W)
R17  value 10.0 k  [RESC1005X06A]  (hidden comment: SM-0402, 1%, 1/16W)
R18  value 15 k  [RESC1005X06A]  (hidden comment: CRCW040215K0FKED)
R19  value 31.6 k  [RESC1005X06A]  (hidden comment: SM-0402, 1%, 1/16W)
R20  value 10.0 k  [RESC1005X06A]  (hidden comment: SM-0402, 1%, 1/16W)
R21  value 15 k  [RESC1005X06A]  (hidden comment: CRCW040215K0FKED)
R22  value 31.6 k  [RESC1005X06A]  (hidden comment: SM-0402, 1%, 1/16W)
R23  value 15 k  [RESC1005X06A]  (hidden comment: CRCW040215K0FKED)
R24  value 10.0 k  [RESC1005X06A]  (hidden comment: SM-0402, 1%, 1/16W)
R25  value 39.2 k  [RESC1005X06A]  (hidden comment: CRCW040239K2FKED)
R26  value 52.3 k  [RESC1005X06A]  (hidden comment: SM-0402, 1%, 1/16W)
R27  value 15 k  [RESC1005X06A]  (hidden comment: CRCW040215K0FKED)
R28  value 374 k  [RESC1005X06A]  (hidden comment: CRCW0402374KFKED)
R29  value 10.0 k  [RESC1005X06A]  (hidden comment: SM-0402, 1%, 1/16W)
R30  value 2.0 k  [RESC1005X06A]  (hidden comment: CRCW04022K00FKED)
R31  value 10.0 k  [RESC1005X06A]  (hidden comment: CRCW040210K0FKED)
TP17  +3.3V_QSFP  [TP-SMD40]
TP18  +3.3V_M.2  [TP-SMD40]
TP19  +3.3V_SZG  [TP-SMD40]
TP20  +5V_SZG  [TP-SMD40]
TP21  TESTPOINT-SMD40  [TP-SMD40]  (value not drawn)
U3  TPS65400RGZT  [PVQFN-48]

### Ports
SZG_I2C (harness I2C)

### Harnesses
I2C: SCL, SDA

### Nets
+3.3V_M.2: C48.2 C49.2 C50.2 C52.2 L2.2 R19.2 TP18.1(PIN)
+3.3V_QSFP: C38.2 C39.2 C40.2 C41.2 L1.2 R16.2 TP17.1(PIN)
+3.3V_SZG: C59.2 C60.2 C61.2 C62.2 L3.2 R22.2 TP19.1(PIN)
+3.3VDD: R30.2
+5V_SZG: C67.2 C68.2 C69.2 C70.2 L4.2 R26.2 TP20.1(PIN)
+VDCIN: C33.1 C34.1 C36.1 C37.2 C46.1 C47.1 C57.1 C58.1 J24.1 J24.2 J24.3 J28.1 U3.5(PVIN1) U3.6(PVIN2) U3.22(VIN) U3.30(PVIN3) U3.31(PVIN4)
DGND: C30.1 C31.1 C32.1 C33.2 C34.2 C36.2 C37.1 C38.1 C39.1 C40.1 C42.2 C43.2 C44.2 C46.2 C47.2 C48.1 C49.1 C50.1 C51.1 C53.2 C54.2 C55.2 C57.2 C58.2 C59.1 C60.1 C61.1 C63.2 C64.2 C65.2 C67.1 C68.1 C69.1 C72.2 C73.1 C74.2 J24.4 J24.5 J24.6 J28.2 Q1.2(S) R17.1 R20.1 R24.1 R25.1 R28.1 R29.1 U3.7(PGND1) U3.8(PGND2) U3.21(AGND) U3.PAD
VDDD: C32.2 R14.2 R15.2 R31.2 U3.20(VDDD)
I2C_SCL: U3.43(SCL) ; port SZG_I2C.SCL
I2C_SDA: U3.42(SDA) ; port SZG_I2C.SDA
SUPPLY_1_CE: R15.1 U3.23(CE)
NetC30_2: C30.2 U3.18(VDDG)
NetC31_2: C31.2 U3.19(VDDA)
NetC35_1: C35.1 U3.1(CB1)
NetC35_2: C35.2 L1.1 U3.2(SW1) U3.3(SW1) U3.4(SW1)
NetC41_1: C41.1 R16.1 R17.2 U3.47(VFB1)
NetC42_1: C42.1 R18.2
NetC43_1: C43.1 U3.45(SS1/PG1)
NetC44_1: C44.1 R18.1 U3.46(COMP1)
NetC45_1: C45.1 U3.12(CB2)
NetC45_2: C45.2 L2.1 U3.9(SW2) U3.10(SW2) U3.11(SW2)
NetC51_2: C51.2 U3.16(SS2/PG2)
NetC52_1: C52.1 R19.1 R20.2 U3.14(VFB2)
NetC53_1: C53.1 R21.2
NetC54_1: C54.1 R21.1 U3.15(COMP2)
NetC55_1: C55.1 U3.24(SS3/PG3)
NetC56_1: C56.1 U3.28(CB3)
NetC56_2: C56.2 L3.1 U3.29(SW3)
NetC62_1: C62.1 R22.1 R24.2 U3.26(VFB3)
NetC63_1: C63.1 U3.37(SS4/PG4)
NetC64_1: C64.1 R23.2
NetC65_1: C65.1 R23.1 U3.25(COMP3)
NetC66_1: C66.1 U3.33(CB4)
NetC66_2: C66.2 L4.1 U3.32(SW4)
NetC70_1: C70.1 R26.1 R29.2 U3.35(VFB4)
NetC71_1: C71.1 TP21.1(PIN)
NetC71_2: C71.2 C73.2 R28.2 U3.40(RCLOCK_SYNC)
NetC72_1: C72.1 R27.2
NetC74_1: C74.1 R27.1 U3.36(COMP4)
NetD1_1: D1.1(K) Q1.3(D)
NetD1_2: D1.2(A) R30.1
NetQ1_1: Q1.1(G) R31.1 U3.17(PGOOD)
NetR14_1: R14.1 U3.39(~{RST})
NetR25_2: R25.2 U3.38(I2CADDR)

Not connected (* = marked no-connect by the designer): J28 3*; U3 13(ENSW2)* 27(ENSW3)* 34(ENSW4)* 41(I2CALERT)* 44(CLK_OUT)* 48(ENSW1/ENSEQ)*

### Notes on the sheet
- Switching Power Supply
- Barrel Jack
- 5A max
- (near J28) 2.5 / 5.1 mm
- +6 to +16 VDC
- 6-pin Mini-Fit
- 8A max
- (near U3) I2C Addr: 1101001
- Power LED
- Title
- Size:
- Date:
- C
- Number:
- Time:
- Revision:
- Sheet
- of

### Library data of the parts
C30 = 001346: Ceramic capacitor; Manufacturer: Taiyo Yuden; partnumber: 001346; Description 2: SM-0603, 20%, 10V, X5R; ValueFloat: 1E-5; Tolerance (%): 20; x_lifecycle_status: Production
C31 = 000824: Ceramic capacitor; Manufacturer: Taiyo Yuden; partnumber: 000824; Description 2: 0402, 6.3V; ValueFloat: 4.7E-6; Tolerance (%): 20
C32 = 001926: Partnumber: 001926; manufacturer: TDK; ValueFloat: 3.3E-6; x_tolerance: 20
C33 C46 C57 = 001172: Ceramic Capacitor; Manufacturer: TDK; partnumber: 001172; Description 2: SM-1206, 35V, 20%; ValueFloat: 2.2E-5; Tolerance (%): 20; x_voltage-rating: 35
C34 C47 C58 = 001073: Ceramic capacitor; Manufacturer: Taiyo Yuden; partnumber: 001073; Description 2: 0402, 25V; ValueFloat: 1E-7; Tolerance (%): 10
C35 C38 C43 C45 C48 C51 C55 C56 C59 C63 C66 C67 = 000070: Ceramic capacitor; Manufacturer: Kemet; partnumber: 000070; Description 2: SM-0402, 10%, 10v; ValueFloat: 1E-7; Tolerance (%): 10
C36 = 001532: Polarized; Partnumber: 001532; manufacturer: Panasonic; ValueFloat: 0.00022; id: 155442; inventory_price: 0.2; x_tolerance: 20; x_voltage-rating: 25
C37 = 001073: Ceramic capacitor; Manufacturer: Taiyo Yuden; partnumber: 001073; Description 2: 0402, 25V; ValueFloat: 1E-7; Tolerance (%): 10; Voltage: 25V
C39 C40 C49 C50 C60 C61 C68 C69 = 001284: Ceramic capacitor; Manufacturer: Taiyo Yuden; partnumber: 001284; Description 2: SM-1206, 10%, 10v, X7R; ValueFloat: 2.2E-5; Tolerance (%): 10; x_lifecycle_status: Production
C41 C52 = 001004: Partnumber: 001004; manufacturer: Kemet; manufacturer_pn: C0402C560J5GACTU; ValueFloat: 5.6E-11; id: 25707; inventory_price: 0.0024; x_temperature_characteristic: C0G; x_tolerance: 5
C42 C53 C64 C72 = 000930: Ceramic capacitor; Manufacturer: Kemet; partnumber: 000930; Description 2: 0402, 50V; ValueFloat: 4.7E-9; Tolerance (%): 10
C44 C54 C65 C74 = 000807: Ceramic capacitor; Manufacturer: Kemet; partnumber: 000807; Description 2: SM-0402, 5%, 50v, C0G; ValueFloat: 2.2E-11; Tolerance (%): 5
C62 C70 = 001004: Ceramic capacitor; Manufacturer: Kemet; partnumber: 001004; Description 2: SM-0402, 5%, 50v; ValueFloat: 5.6E-11; Tolerance (%): 5
C71 = 000400: Partnumber: 000400; manufacturer: Kemet; manufacturer_pn: C0402C101J5GACTU; ValueFloat: 1E-10; id: 3829; inventory_price: 0.003; reorder_quantity: 200
C73 = 000962: Ceramic capacitor; Manufacturer: Murata; partnumber: 000962; Description 2: SM-0402, 50V; ValueFloat: 5E-12; Tolerance (%): 3.125
D1 = 001433: LED; Manufacturer: Dialight; Manufacturer_PN: 598-8070-107F; partnumber: 001433; Description 2: SM-0603, green; x_lifecycle_status: Production
J24 = 001950: Partnumber: 001950; manufacturer: Molex
J28 = DCPOWER: DC power connector - high current; manufacturer: CUI Inc.; partnumber: 000356
L1 L2 = 001543: Power inductor, 2.2uH, 7A, 12.7mOhm; Manufacturer: Coilcraft; partnumber: 001543; ValueFloat: 2.2E-6; Tolerance (%): 20; x_lifecycle_status: Production
L3 L4 = 002384: Partnumber: 002384; manufacturer: TDK; ValueFloat: 2.2E-6; x_tolerance: 20
Q1 = 001237: N-Channel MOSFET; PartNumber: 001237; manufacturer: Fairchild Semiconductor; manufacturer_pn: FDN337N; PackageDocument: 1995/1996; id: 48493; inventory_price: 0.2466
R14 R15 R31 = 001521: as R58 on sheet Transceiver-QSFP
R16 R19 R22 = 001091: Partnumber: 001091; manufacturer: Vishay; manufacturer_pn: CRCW040231K6FKED; ValueFloat: 31600; id: 32220; inventory_price: 0.0015; x_tolerance: 1
R17 R20 R24 R29 = 001521: as R3 on sheet MC1
R18 R21 R23 R27 = 001121: Thick-film resistor; Manufacturer: Vishay; partnumber: 001121; Description 2: SM-0402, 1%, 1/16W; ValueFloat: 15000; Tolerance (%): 1
R25 = 001122: Partnumber: 001122; manufacturer: Vishay; ValueFloat: 39200; x_tolerance: 1
R26 = 001157: Partnumber: 001157; manufacturer: Vishay; manufacturer_pn: CRCW040252K3FKED; ValueFloat: 52300; id: 36019; inventory_price: 0.0019; x_tolerance: 1
R28 = 001618: Thick-film resistor; Manufacturer: Vishay; partnumber: 001618; Description 2: SM-0402, 1%, 1/16W; ValueFloat: 374000; Tolerance (%): 1; x_lifecycle_status: Production
R30 = 001162: Thick-film resistor; Manufacturer: Vishay; partnumber: 001162; Description 2: SM-0402, 1%, 1/16W; ValueFloat: 2000; Tolerance (%): 1
TP17-TP21 = TESTPOINT-SMD40: Test point, surface-mount, 40mil
U3 = 001511: 4-channel switching regulator with PMBus; Manufacturer: Texas Instruments; partnumber: 001511; Description 2: Vin: 4.5V to 18V, Vout: 0.6V to 90% Vin,PMBus, VQFN-48; x_lifecycle_status: Production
